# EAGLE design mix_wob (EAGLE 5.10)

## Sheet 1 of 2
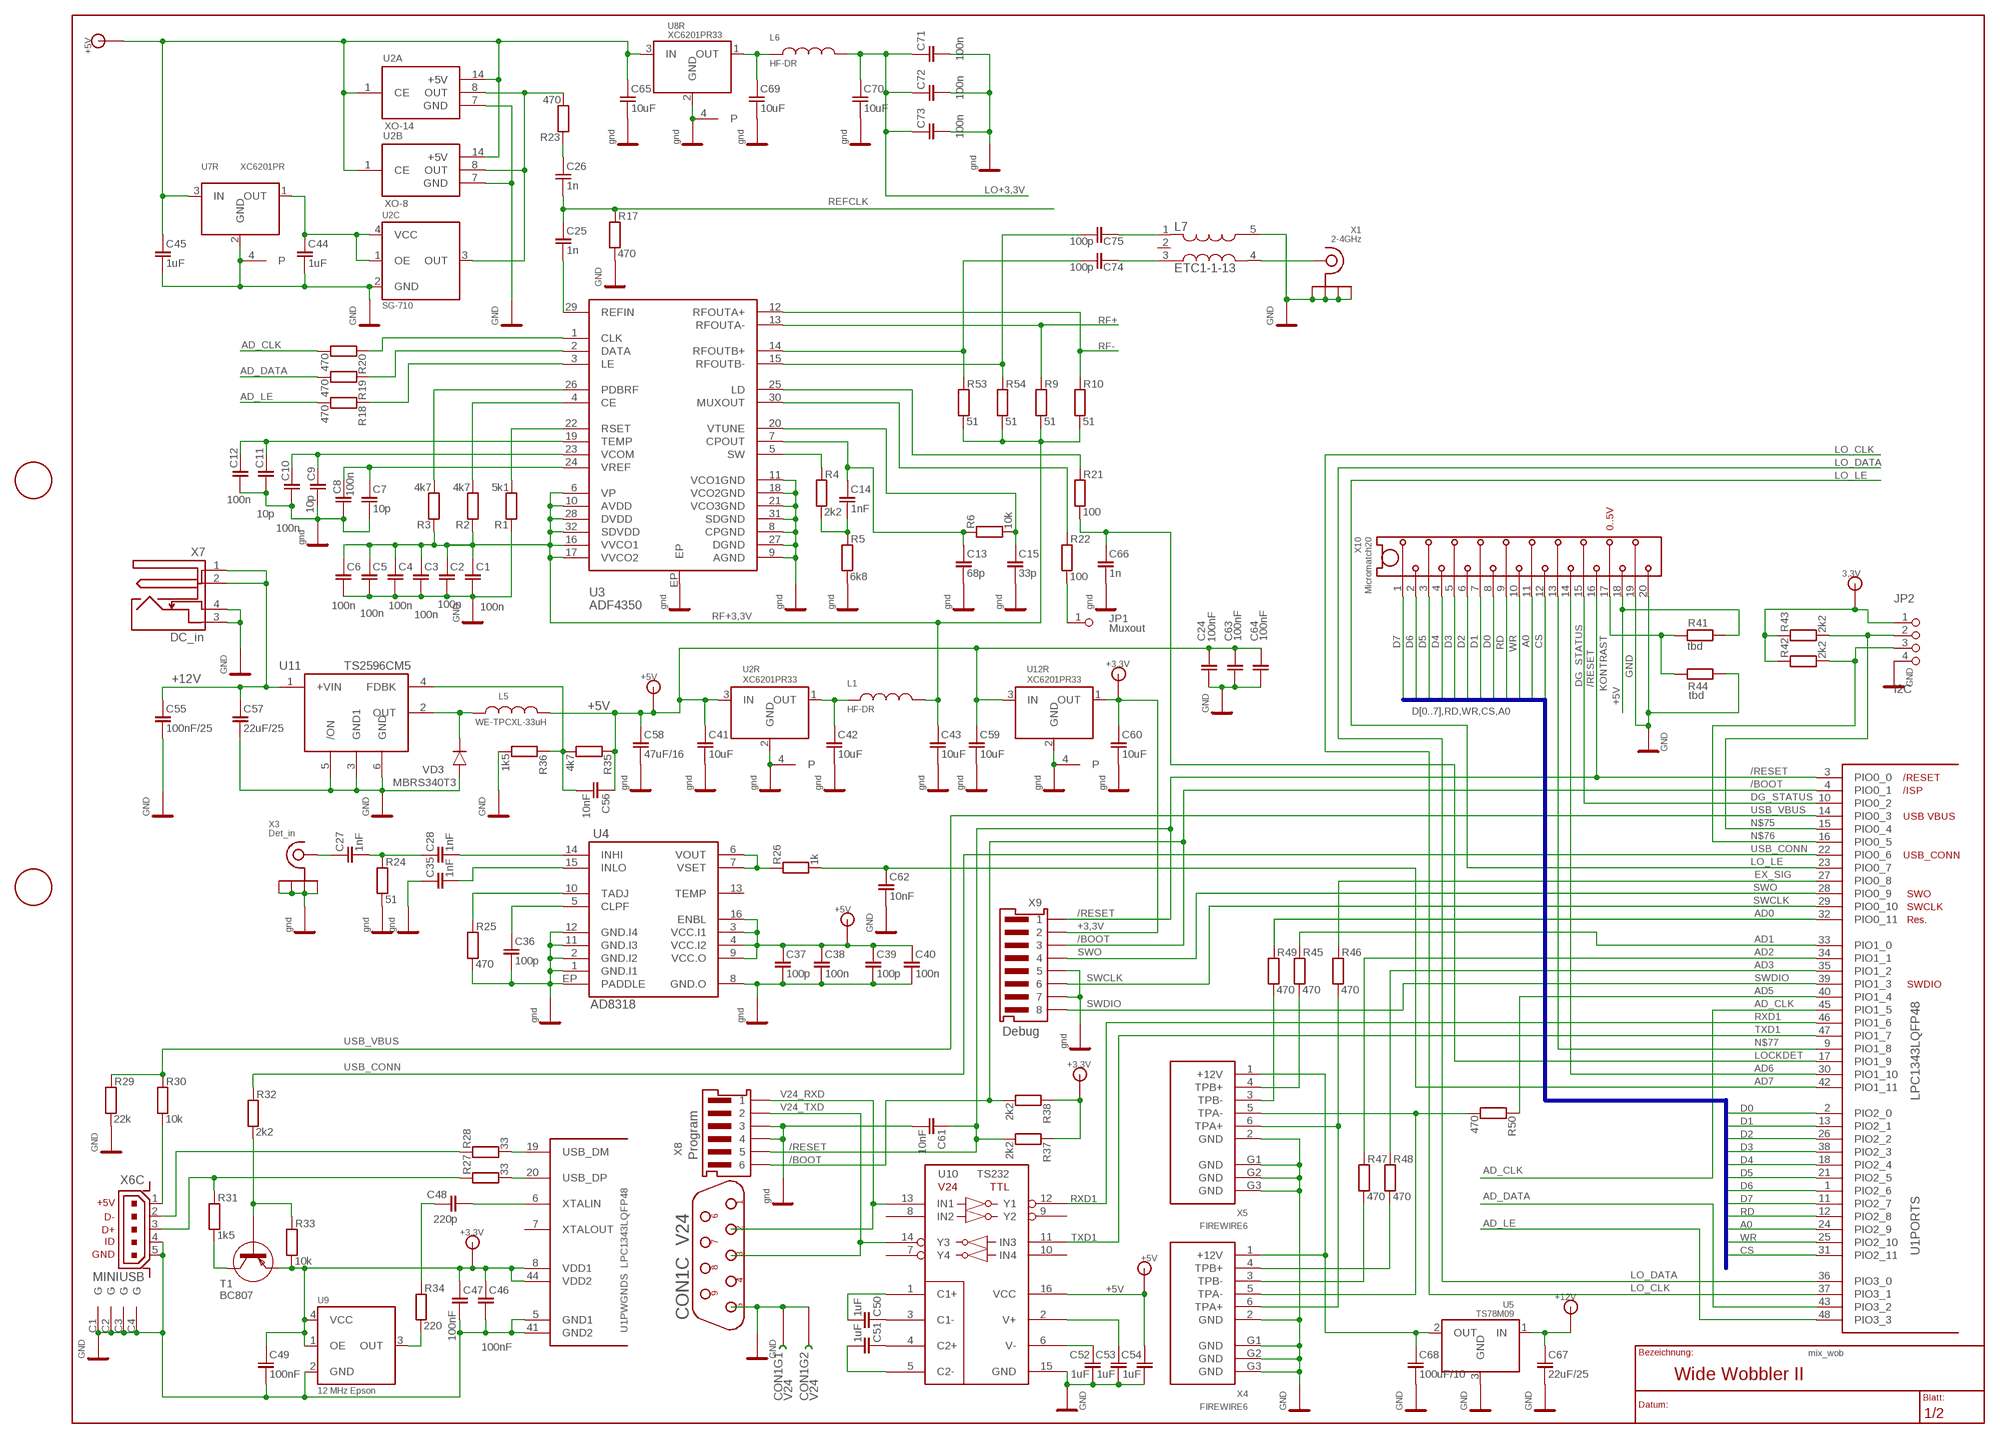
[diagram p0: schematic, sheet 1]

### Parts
C1  100n  SMD-0603  [SOT-0603]
C2  100n  SMD-0603  [SOT-0603]
C3  100n  SMD-0603  [SOT-0603]
C4  100n  SMD-0603  [SOT-0603]
C5  100n  SMD-0603  [SOT-0603]
C6  100n  SMD-0603  [SOT-0603]
C7  10p  SMD-0603  [SOT-0603]
C8  100n  SMD-0603  [SOT-0603]
C9  10p  SMD-0603  [SOT-0603]
C10  100n  SMD-0603  [SOT-0603]
C11  10p  SMD-0603  [SOT-0603]
C12  100n  SMD-0603  [SOT-0603]
C13  68p  SMD-0603  [SOT-0603]
C14  1nF  SMD-0603  [SOT-0603]
C15  33p  SMD-0603  [SOT-0603]
C24  100nF  SMD-0603  [SOT-0603]
C25  1n  SMD-0603  [SOT-0603]
C26  1n  SMD-0603  [SOT-0603]
C27  1nF  SMD-0603  [SOT-0603]
C28  1nF  SMD-0603  [SOT-0603]
C35  1nF  SMD-0603  [SOT-0603]
C36  100p  SMD-0603  [SOT-0603]
C37  100p  SMD-0603  [SOT-0603]
C38  100n  SMD-0603  [SOT-0603]
C39  100p  SMD-0603  [SOT-0603]
C40  100n  SMD-0603  [SOT-0603]
C41  10uF  SMD-0805  [SOT-0805]
C42  10uF  SMD-0805  [SOT-0805]
C43  10uF  SMD-0805  [SOT-0805]
C44  1uF  SMD-0805  [SOT-0805]
C45  1uF  SMD-0805  [SOT-0805]
C46  100nF  SMD-0603  [SOT-0603]
C47  100nF  SMD-0603  [SOT-0603]
C48  220p  SMD-0603  [SOT-0603]
C49  100nF  SMD-0603  [SOT-0603]
C50  1uF  SMD-0805  [SOT-0805]
C51  1uF  SMD-0805  [SOT-0805]
C52  1uF  SMD-0805  [SOT-0805]
C53  1uF  SMD-0805  [SOT-0805]
C54  1uF  SMD-0805  [SOT-0805]
C55  100nF/25  SMD-0805  [SOT-0805]
C56  10nF  SMD-0805  [SOT-0805]
C57  22uF/25  SMD-1210  [SOT-1210]
C58  47uF/16  SMD-1210  [SOT-1210]
C59  10uF  SMD-0805  [SOT-0805]
C60  10uF  SMD-0805  [SOT-0805]
C61  10nF  SMD-0603  [SOT-0603]
C62  10nF  SMD-0603  [SOT-0603]
C63  100nF  SMD-0603  [SOT-0603]
C64  100nF  SMD-0603  [SOT-0603]
C65  10uF  SMD-0805  [SOT-0805]
C66  1n  SMD-0603  [SOT-0603]
C67  22uF/25  SMD-1210  [SOT-1210]
C68  100uF/10  SMD-1210  [SOT-1210]
C69  10uF  SMD-0805  [SOT-0805]
C70  10uF  SMD-0805  [SOT-0805]
C71  100n  SMD-0603  [SOT-0603]
C72  100n  SMD-0603  [SOT-0603]
C73  100n  SMD-0603  [SOT-0603]
C74  100p  SMD-0603  [SOT-0603]
C75  100p  SMD-0603  [SOT-0603]
CON1  V24  DB9M/90  [DZ09M/90]
JP1  Muxout  PINHD-1X1  [1X01]
JP2  I2C  PINHD-1X4  [1X04]
L1  HF-DR  SMD-0805  [SMD-0805]
L5  WE-TPCXL-33uH  WE-TPCXL  [WE-TPCXL]
L6  HF-DR  SMD-0805  [SMD-0805]
L7  ETC1-1-13  [ETC1-1-13]
R1  5k1  SMD-0603  [SMD-0603]
R2  4k7  SMD-0603  [SMD-0603]
R3  4k7  SMD-0603  [SMD-0603]
R4  2k2  SMD-0603  [SMD-0603]
R5  6k8  SMD-0603  [SMD-0603]
R6  10k  SMD-0603  [SMD-0603]
R9  51  SMD-0603  [SMD-0603]
R10  51  SMD-0603  [SMD-0603]
R17  470  SMD-0603  [SMD-0603]
R18  470  SMD-0603  [SMD-0603]
R19  470  SMD-0603  [SMD-0603]
R20  470  SMD-0603  [SMD-0603]
R21  100  SMD-0603  [SMD-0603]
R22  100  SMD-0603  [SMD-0603]
R23  470  SMD-0603  [SMD-0603]
R24  51  SMD-0603  [SMD-0603]
R25  470  SMD-0603  [SMD-0603]
R26  1k  SMD-0603  [SMD-0603]
R27  33  SMD-0603  [SMD-0603]
R28  33  SMD-0603  [SMD-0603]
R29  22k  SMD-0603  [SMD-0603]
R30  10k  SMD-0603  [SMD-0603]
R31  1k5  SMD-0603  [SMD-0603]
R32  2k2  SMD-0603  [SMD-0603]
R33  10k  SMD-0603  [SMD-0603]
R34  220  SMD-0603  [SMD-0603]
R35  4k7  SMD-0805  [SMD-0805]
R36  1k5  SMD-0805  [SMD-0805]
R37  2k2  SMD-0603  [SMD-0603]
R38  2k2  SMD-0603  [SMD-0603]
R41  tbd  SMD-0603  [SMD-0603]
R42  2k2  SMD-0603  [SMD-0603]
R43  2k2  SMD-0603  [SMD-0603]
R44  tbd  SMD-0603  [SMD-0603]
R45  470  SMD-0603  [SMD-0603]
R46  470  SMD-0603  [SMD-0603]
R47  470  SMD-0603  [SMD-0603]
R48  470  SMD-0603  [SMD-0603]
R49  470  SMD-0603  [SMD-0603]
R50  470  SMD-0603  [SMD-0603]
R53  51  SMD-0603  [SMD-0603]
R54  51  SMD-0603  [SMD-0603]
T1  BC807  BC807-40  [SOT-23]
U1  LPC1343LQFP48  LPC13XXLQFP48  [LQFP48]
U2  XC6201PR33  XC6201-PR  [SOT89]
U2A  XO-14  QU-OSZ14  [OSC]
U2B  XO-8  QU-OSZ8  [OSC-KURZ]
U2C  SG-710  [SG710]
U3  ADF4350  ADF4350CP-32-2  [CP32-2]
U4  AD8318  [CP16-4]
U5  TS78M09  TS78MXX  [DPAK]
U7  XC6201PR  XC6201-PR  [SOT89]
U8  XC6201PR33  XC6201-PR  [SOT89]
U9  12 MHz Epson  SG-710  [SG710]
U10  TS232  MAX-232CWE  [SO-16W]
U11  TS2596CM5  [TO263-5L]
U12  XC6201PR33  XC6201-PR  [SOT89]
VD3  MBRS340T3  [SMC]
X1  2-4GHz  SMA-EDGE'KANTE'  [SMA-EDGE]
X3  Det_in  SMA-EDGE'KANTE'  [SMA-EDGE]
X4  FIREWIRE6  [IEEE1394-6V]
X5  FIREWIRE6  [IEEE1394-6V]
X6  MINIUSB  [UX60A-MB-5SY]
X7  DC_in  DC-10-XX  [DC-10-XX]
X8  Program  LUMBG6  [LUMBG6]
X9  Debug  LUMBG8  [LUMBG8]
X10  Micromatch20  MICMATCH20  [MIMA20]

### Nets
+3,3V: C46.2 C47.2 C49.2 C60.2 JP2.1 R33.1 R37.2 R38.2 R42.2 R43.2 T1.2(E) U1.8(PWGNDS:VDD1) U1.44(PWGNDS:VDD2) U9.1(OE) U9.4(VCC) U12.1(R:OUT) X9.2 ; supply symbol labelled 3,3V
+3,3V_XO: C44.2 U2C.1(OE) U2C.4(VCC) U7.1(R:OUT)
+5V: C24.2 C37.2 C38.2 C39.2 C40.2 C41.2 C45.2 C54.2 C56.2 C58.2 C59.2 C63.2 C64.2 C65.2 L5.2 R35.2 R41.2 U2.3(R:IN) U2A.1(CE) U2A.14(+5V) U2B.1(CE) U2B.14(+5V) U4.3(VCC.I1) U4.4(VCC.I2) U4.9(VCC.O) U4.16(ENBL) U7.3(R:IN) U8.3(R:IN) U10.16(VCC) U12.3(R:IN) X10.18
+9VOLT: C68.2 U5.2(OUT) X4.1(+12V) X5.1(+12V)
+12V: C55.2 C57.2 C67.2 U5.1(IN) U11.1(+VIN) X7.1 X7.2
/BOOT: R38.1 U1.4(PORTS:PIO0_1) X8.6 X9.3
/RESET: C61.2 R37.1 U1.3(PORTS:PIO0_0) X8.5 X9.1 X10.16
A0: U1.24(PORTS:PIO2_9) X10.11
AD0: R49.2 U1.32(PORTS:PIO0_11)
AD1: R45.2 U1.33(PORTS:PIO1_0)
AD2: R47.2 U1.34(PORTS:PIO1_1)
AD3: R48.2 U1.35(PORTS:PIO1_2)
AD5: R50.2 U1.40(PORTS:PIO1_4)
AD6: U1.30(PORTS:PIO1_10) X10.14
AD7: C62.2 R26.1 U1.42(PORTS:PIO1_11)
AD_CLK: R20.1 U1.45(PORTS:PIO1_5)
AD_DATA: R19.1 U1.43(PORTS:PIO3_2)
AD_LE: R18.1 U1.48(PORTS:PIO3_3)
CS: U1.31(PORTS:PIO2_11) X10.12
D0: U1.2(PORTS:PIO2_0) X10.8
D1: U1.13(PORTS:PIO2_1) X10.7
D2: U1.26(PORTS:PIO2_2) X10.6
D3: U1.38(PORTS:PIO2_3) X10.5
D4: U1.18(PORTS:PIO2_4) X10.4
D5: U1.21(PORTS:PIO2_5) X10.3
D6: U1.1(PORTS:PIO2_6) X10.2
D7: U1.11(PORTS:PIO2_7) X10.1
DG_STATUS: U1.10(PORTS:PIO0_2) X10.15
EX_SIG: R46.2 U1.27(PORTS:PIO0_8)
F_REF: C26.2 R23.2
GND: C1.1 C2.1 C3.1 C4.1 C5.1 C6.1 C7.1 C8.1 C9.1 C10.1 C11.1 C12.1 C13.1 C15.1 C24.1 C35.2 C36.1 C37.1 C38.1 C39.1 C40.1 C41.1 C42.1 C43.1 C44.1 C45.1 C46.1 C47.1 C49.1 C52.1 C53.1 C54.1 C55.1 C57.1 C58.1 C59.1 C60.1 C61.1 C62.1 C63.1 C64.1 C65.1 C66.1 C67.1 C68.1 C69.1 C70.1 C71.1 C72.1 C73.1 CON1.5 CON1.G1 CON1.G2 JP2.4 L7.5 R1.2 R5.1 R17.1 R24.1 R25.1 R29.1 R36.1 R44.1 U1.5(PWGNDS:GND1) U1.41(PWGNDS:GND2) U2.2(R:GND) U2.4(P) U2A.7(GND) U2B.7(GND) U2C.2(GND) U3.8(CPGND) U3.9(AGND) U3.11(VCO1GND) U3.18(VCO2GND) U3.21(VCO3GND) U3.27(DGND) U3.31(SDGND) U3.EP U4.1(GND.I1) U4.2(GND.I2) U4.8(GND.O) U4.11(GND.I3) U4.12(GND.I4) U4.EP(PADDLE) U5.3(GND) U7.2(R:GND) U7.4(P) U8.2(R:GND) U8.4(P) U9.2(GND) U10.15(GND) U11.3(GND1) U11.5(/ON) U11.6(GND) U12.2(R:GND) U12.4(P) VD3.A X1.GND@1(GND) X1.GND@2(GND) X1.GND@3(GND) X1.GND@4(GND) X3.GND@1(GND) X3.GND@2(GND) X3.GND@3(GND) X3.GND@4(GND) X4.2(GND) X4.G1(GND) X4.G2(GND) X4.G3(GND) X5.2(GND) X5.G1(GND) X5.G2(GND) X5.G3(GND) X6.4 X6.5 X6.C1(G) X6.C2(G) X6.C3(G) X6.C4(G) X7.3 X7.4 X8.3 X8.4 X9.5 X9.7 X10.19 X10.20 ; supply symbol labelled gnd ; also sheet 2
KONTRAST: R41.1 R44.2 X10.17
LO+3,3V: C70.2 C71.2 C72.2 C73.2 L6.2 ; also sheet 2
LO_CLK: U1.37(PORTS:PIO3_1) ; also sheet 2
LO_DATA: U1.36(PORTS:PIO3_0) ; also sheet 2
LO_LE: U1.23(PORTS:PIO0_7) ; also sheet 2
LOCKDET: C66.2 R21.1 U1.17(PORTS:PIO1_9)
N$1: R18.2 U3.3(LE)
N$2: C7.2 C8.2 U3.24(VREF)
N$3: C9.2 C10.2 U3.23(VCOM)
N$4: C11.2 C12.2 U3.19(TEMP)
N$5: R1.1 U3.22(RSET)
N$7: R2.1 U3.4(CE)
N$8: R3.1 U3.26(PDBRF)
N$9: C15.2 R6.1 U3.20(VTUNE)
N$10: C14.1 R4.1 R5.2
N$11: R4.2 U3.5(SW)
N$12: C13.2 C14.2 R6.2 U3.7(CPOUT)
N$14: R19.2 U3.2(DATA)
N$15: R20.2 U3.1(CLK)
N$36: C69.2 L6.1 U8.1(R:OUT)
N$37: C75.2 L7.1
N$38: L7.4 X1.A
N$39: C74.2 L7.3
N$40: C25.1 U3.29(REFIN)
N$42: R21.2 U3.25(LD)
N$43: R22.2 U3.30(MUXOUT)
N$44: R23.1 U2A.8(OUT) U2B.8(OUT) U2C.3(OUT)
N$45: C27.2 X3.A
N$46: C27.1 C28.2 R24.2
N$47: C28.1 U4.14(INHI)
N$48: C35.1 U4.15(INLO)
N$49: C36.2 U4.5(CLPF)
N$50: R25.2 U4.10(TADJ)
N$51: R26.2 U4.6(VOUT) U4.7(VSET)
N$52: C42.2 L1.1 U2.1(R:OUT)
N$53: R27.2 R31.2 X6.3
N$54: R28.2 X6.2
N$55: R30.1 X6.1
N$56: R28.1 U1.19(PWGNDS:USB_DM)
N$57: R27.1 U1.20(PWGNDS:USB_DP)
N$58: R31.1 T1.3(C)
N$59: R32.1 R33.2 T1.1(B)
N$60: C48.1 U1.6(PWGNDS:XTALIN)
N$61: C48.2 R34.2
N$62: R34.1 U9.3(OUT)
N$63: C50.1 U10.1(C1+)
N$64: C50.2 U10.3(C1-)
N$65: C51.2 U10.4(C2+)
N$66: C51.1 U10.5(C2-)
N$67: C52.2 U10.6(V-)
N$68: C53.2 U10.2(V+)
N$70: JP1.1 R22.1
N$71: C75.1 R54.2 U3.15(RFOUTB-)
N$72: C74.1 R53.2 U3.14(RFOUTB+)
N$73: L5.1 U11.2(OUT) VD3.K
N$74: C56.1 R35.1 R36.2 U11.4(FDBK)
N$75: JP2.2 R43.1 U1.15(PORTS:PIO0_4)
N$76: JP2.3 R42.1 U1.16(PORTS:PIO0_5)
N$77: U1.9(PORTS:PIO1_8) X10.13
N$78: R48.1 X4.4(TPB+)
N$79: R47.1 X4.3(TPB-)
N$80: R45.1 X5.4(TPB+)
N$81: R49.1 X5.3(TPB-)
N$82: R46.1 X4.6(TPA+) X5.6(TPA+)
N$83: R50.1 X4.5(TPA-) X5.5(TPA-)
RD: U1.12(PORTS:PIO2_8) X10.9
REFCLK: C25.2 C26.1 R17.2 ; also sheet 2
RF+: R9.2 U3.13(RFOUTA-) ; also sheet 2
RF+3,3V: C1.2 C2.2 C3.2 C4.2 C5.2 C6.2 C43.2 L1.2 R2.2 R3.2 R9.1 R10.1 R53.1 R54.1 U3.6(VP) U3.10(AVDD) U3.16(VVCO1) U3.17(VVCO2) U3.28(DVDD) U3.32(SDVDD)
RF-: R10.2 U3.12(RFOUTA+) ; also sheet 2
RXD1: U1.46(PORTS:PIO1_6) U10.12(Y1)
SWCLK: U1.29(PORTS:PIO0_10) X9.6
SWDIO: U1.39(PORTS:PIO1_3) X9.8
SWO: U1.28(PORTS:PIO0_9) X9.4
TXD1: U1.47(PORTS:PIO1_7) U10.11(IN3)
USB_CONN: R32.2 U1.22(PORTS:PIO0_6)
USB_VBUS: R29.2 R30.2 U1.14(PORTS:PIO0_3)
V24_RXD: CON1.2 U10.13(IN1) X8.1
V24_TXD: CON1.3 U10.14(Y3) X8.2
WR: U1.25(PORTS:PIO2_10) X10.10
Unconnected: CON1.1 CON1.4 CON1.6 CON1.7 CON1.8 CON1.9 L7.2 U1.7(PWGNDS:XTALOUT) U4.13(TEMP) U10.7(Y4) U10.8(IN2) U10.9(Y2) U10.10(IN4)

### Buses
D[0..7],RD,WR,CS,A0

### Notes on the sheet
- 0..5V
- Wide Wobbler II

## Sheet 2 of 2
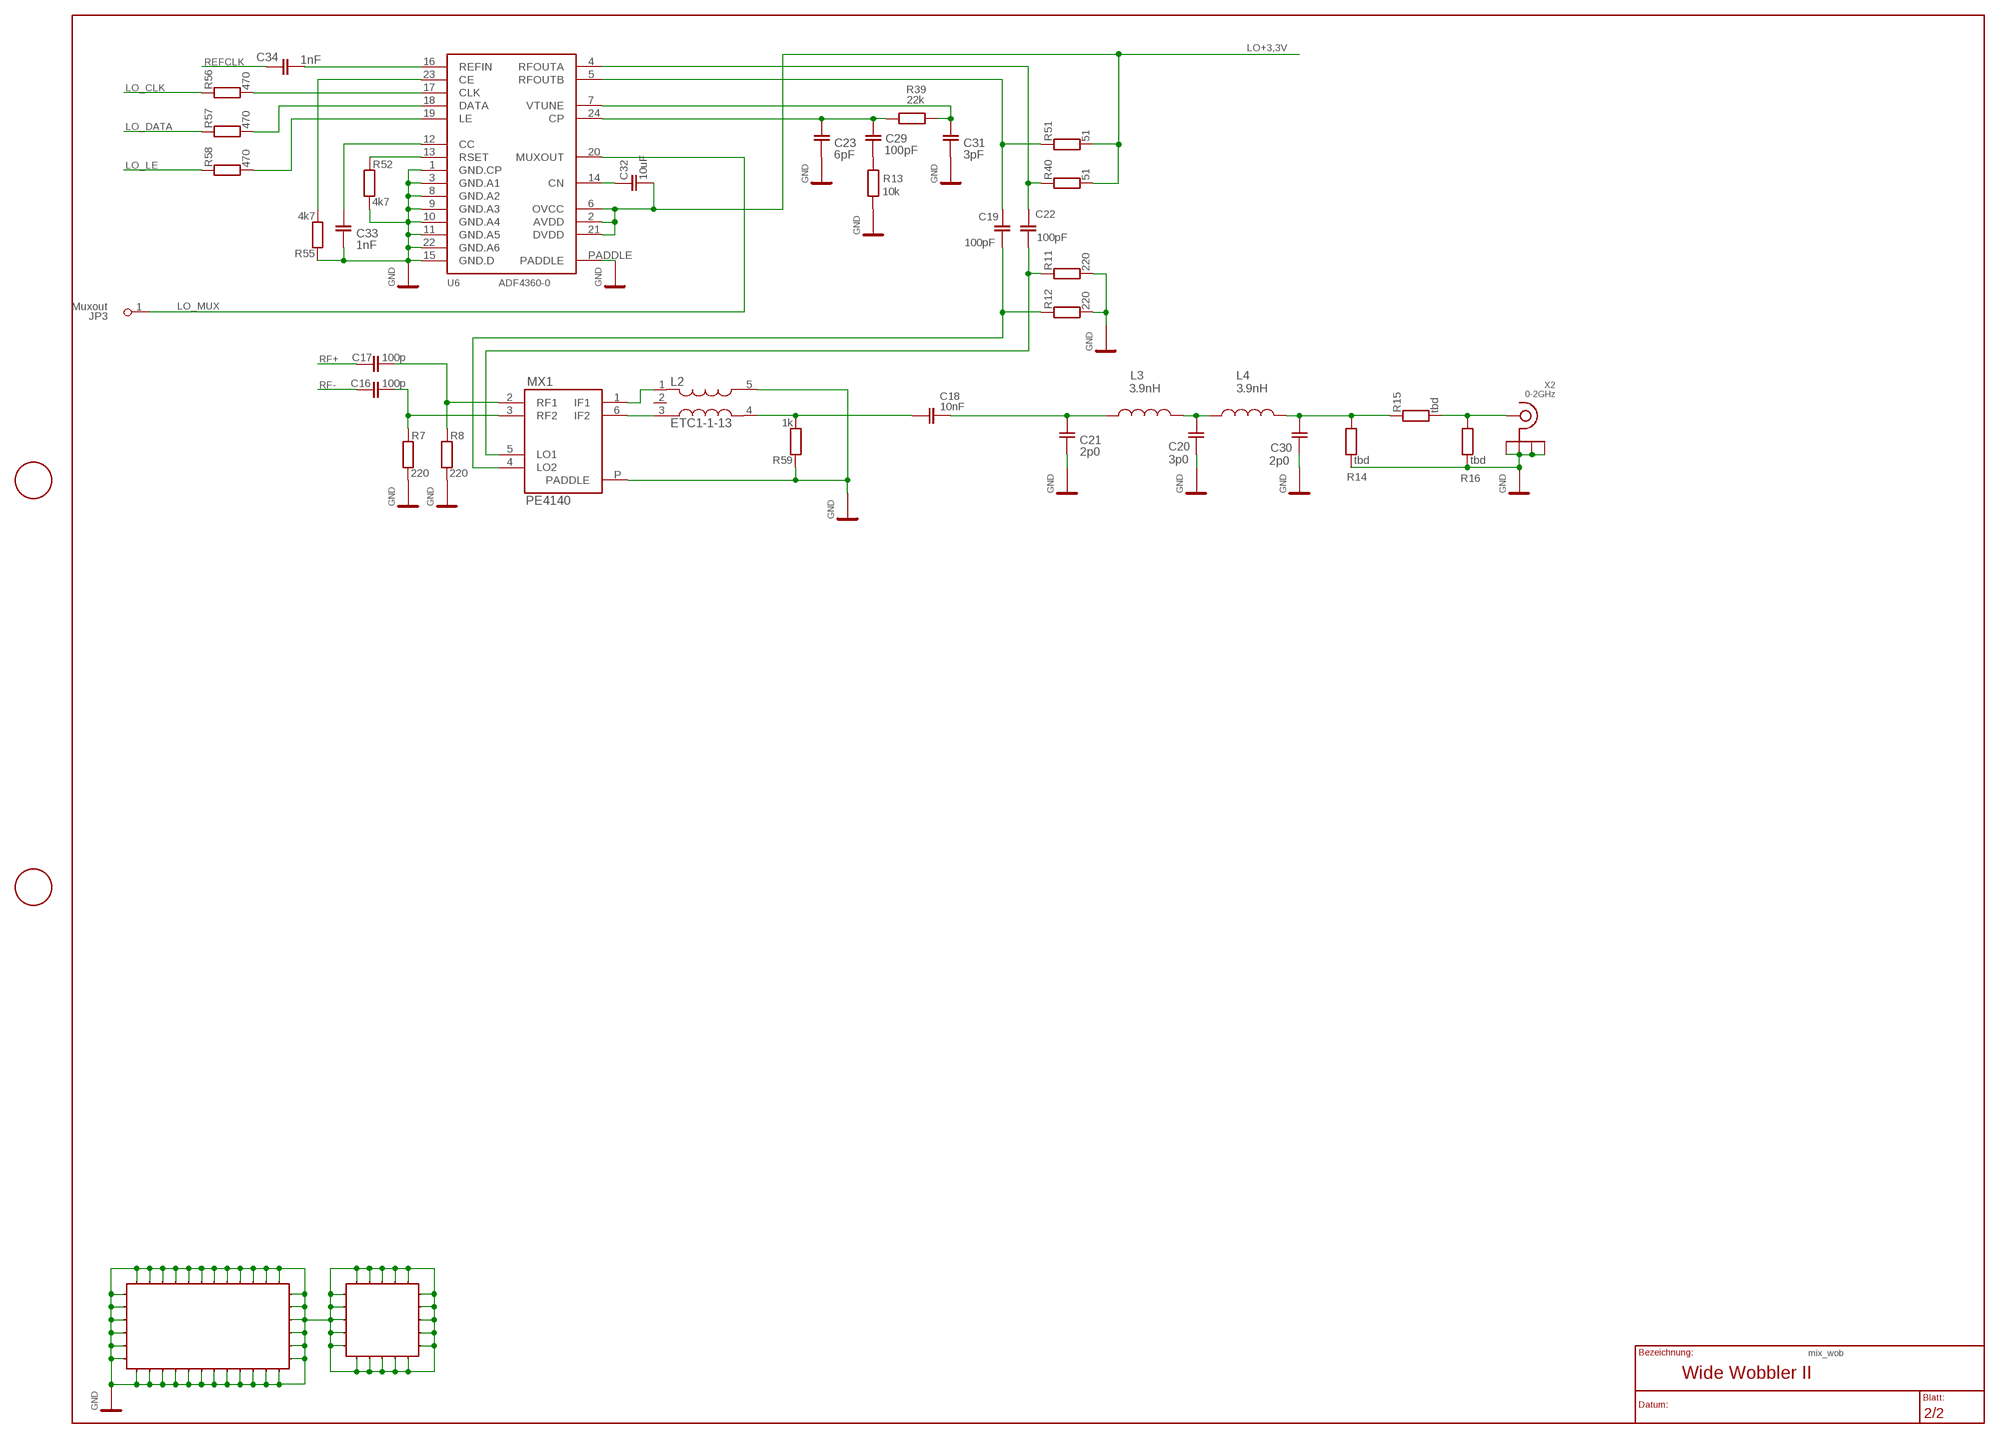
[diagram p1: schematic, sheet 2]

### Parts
C16  100p  SMD-0603  [SOT-0603]
C17  100p  SMD-0603  [SOT-0603]
C18  10nF  SMD-0603  [SOT-0603]
C19  100pF  SMD-0603  [SOT-0603]
C20  3p0  SMD-0603  [SOT-0603]
C21  2p0  SMD-0603  [SOT-0603]
C22  100pF  SMD-0603  [SOT-0603]
C23  6pF  SMD-0603  [SOT-0603]
C29  100pF  SMD-0603  [SOT-0603]
C30  2p0  SMD-0603  [SOT-0603]
C31  3pF  SMD-0603  [SOT-0603]
C32  10uF  SMD-0805  [SOT-0805]
C33  1nF  SMD-0603  [SOT-0603]
C34  1nF  SMD-0603  [SOT-0603]
JP3  Muxout  PINHD-1X1  [1X01]
L2  ETC1-1-13  [ETC1-1-13]
L3  3.9nH  SMD-0603  [SMD-0603]
L4  3.9nH  SMD-0603  [SMD-0603]
MX1  PE4140  [PE4140]
R7  220  SMD-0603  [SMD-0603]
R8  220  SMD-0603  [SMD-0603]
R11  220  SMD-0603  [SMD-0603]
R12  220  SMD-0603  [SMD-0603]
R13  10k  SMD-0603  [SMD-0603]
R14  tbd  SMD-0603  [SMD-0603]
R15  tbd  SMD-0603  [SMD-0603]
R16  tbd  SMD-0603  [SMD-0603]
R39  22k  SMD-0603  [SMD-0603]
R40  51  SMD-0603  [SMD-0603]
R51  51  SMD-0603  [SMD-0603]
R52  4k7  SMD-0603  [SMD-0603]
R55  4k7  SMD-0603  [SMD-0603]
R56  470  SMD-0603  [SMD-0603]
R57  470  SMD-0603  [SMD-0603]
R58  470  SMD-0603  [SMD-0603]
R59  1k  SMD-0603  [SMD-0603]
S1  Shield-Gen  S31-62  [AK31X62]
S2  Shield-Det  S25-25  [AK25X25]
U6  ADF4360-0  ADF4360-X  [CP-24-3]
X2  0-2GHz  SMA-EDGE'KANTE'  [SMA-EDGE]

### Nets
GND: C20.1 C21.1 C23.1 C30.2 C31.1 C33.1 L2.5 MX1.P(PADDLE) R7.1 R8.1 R11.1 R12.1 R13.1 R14.1 R16.1 R52.1 R55.2 R59.2 S1.1 S1.2 S1.3 S1.4 S1.5 S1.6 S1.7 S1.8 S1.9 S1.10 S1.11 S1.12 S1.13 S1.14 S1.15 S1.16 S1.17 S1.18 S1.19 S1.20 S1.21 S1.22 S1.23 S1.24 S1.25 S1.26 S1.27 S1.28 S1.29 S1.30 S1.31 S1.32 S1.33 S1.34 S1.35 S1.36 S2.1 S2.2 S2.3 S2.4 S2.5 S2.6 S2.7 S2.8 S2.9 S2.10 S2.11 S2.12 S2.13 S2.14 S2.15 S2.16 S2.17 S2.18 S2.19 S2.20 U6.1(GND.CP) U6.3(GND.A1) U6.8(GND.A2) U6.9(GND.A3) U6.10(GND.A4) U6.11(GND.A5) U6.15(GND.D) U6.22(GND.A6) U6.PADDLE X2.GND@1(GND) X2.GND@2(GND) X2.GND@3(GND) X2.GND@4(GND) ; also sheet 1
LO+3,3V: C32.1 R40.1 R51.1 U6.2(AVDD) U6.6(OVCC) U6.21(DVDD) ; also sheet 1
LO_CLK: R56.2 ; also sheet 1
LO_DATA: R57.2 ; also sheet 1
LO_LE: R58.2 ; also sheet 1
LO_MUX: JP3.1 U6.20(MUXOUT)
N$6: R55.1 U6.23(CE)
N$13: L2.3 MX1.6(IF2)
N$16: R56.1 U6.17(CLK)
N$17: R57.1 U6.18(DATA)
N$18: L2.1 MX1.1(IF1)
N$19: C22.2 R40.2 U6.4(RFOUTA)
N$20: C16.1 MX1.3(RF2) R7.2
N$21: C17.1 MX1.2(RF1) R8.2
N$22: C30.1 L4.2 R14.2 R15.2
N$23: C19.2 R51.2 U6.5(RFOUTB)
N$24: C18.1 C21.2 L3.1
N$25: C20.2 L3.2 L4.1
N$26: C22.1 MX1.5(LO1) R11.2
N$27: R15.1 R16.2 X2.A
N$28: C19.1 MX1.4(LO2) R12.2
N$29: C29.1 R13.2
N$30: C23.2 C29.2 R39.2 U6.24(CP)
N$31: C31.2 R39.1 U6.7(VTUNE)
N$32: C32.2 U6.14(CN)
N$33: R52.2 U6.13(RSET)
N$34: C33.2 U6.12(CC)
N$35: C34.1 U6.16(REFIN)
N$41: R58.1 U6.19(LE)
N$69: C18.2 L2.4 R59.1
REFCLK: C34.2 ; also sheet 1
RF+: C17.2 ; also sheet 1
RF-: C16.2 ; also sheet 1
Unconnected: L2.2

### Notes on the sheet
- Wide Wobbler II

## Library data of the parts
C1-C31 C33-C40 C46-C49 C61-C64 C66 C71-C75 = C_KERAM:SMD-0603
C32 C41-C45 C50-C56 C59 C60 C65 C69 C70 = C_KERAM:SMD-0805
C57 C58 C67 C68 = C_KERAM:SMD-1210
CON1 = Z_CONNEC:DB9M/90
JP1 JP3 = PINHD-Q:PINHD-1X1
JP2 = PINHD-Q:PINHD-1X4
L1 L6 = L:SMD-0805
L2 L7 = HAMRAD:ETC1-1-13: MACOM Transmission-Line Balun 4.5 - 3000 MHz
L3 L4 = L:SMD-0603
L5 = L:WE-TPCXL
MX1 = HAMRAD:PE4140: MOSFET-Array
R1-R34 R37-R59 = R:SMD-0603
R35 R36 = R:SMD-0805
S1 = SHIELDS:S31-62
S2 = SHIELDS:S25-25
T1 = TR_PNP:BC807-40
U1 = philips:LPC13XX
U2 U7 U8 U12 = TOREX:XC6201-PR
U2A = Z_SPECIA:QU-OSZ14
U2B = Z_SPECIA:QU-OSZ8
U2C U9 = SEIK_EPS:SG-710
U3 = ANALOG_D:ADF4350: 4.4 GHz Synthesizer mit integriertem VCO
U4 = ANALOG_D:AD8318
U5 = TSC:TS78MXX
U6 = HAMRAD:ADF4360-X
U10 = MAXIM:MAX-232CWE
U11 = TSC:TS2596CM5
VD3 = DIODEN:MBRS340T3
X1-X3 = HAMRAD:SMA-EDGE
X4 X5 = Z_CONNEC:FIREWIRE6
X6 = mini-usb:MINIUSB
X7 = Z_CONNEC:DC-10-XX
X8 = Z_CONNEC:LUMBG6
X9 = Z_CONNEC:LUMBG8
X10 = TYCO:MICMATCH20

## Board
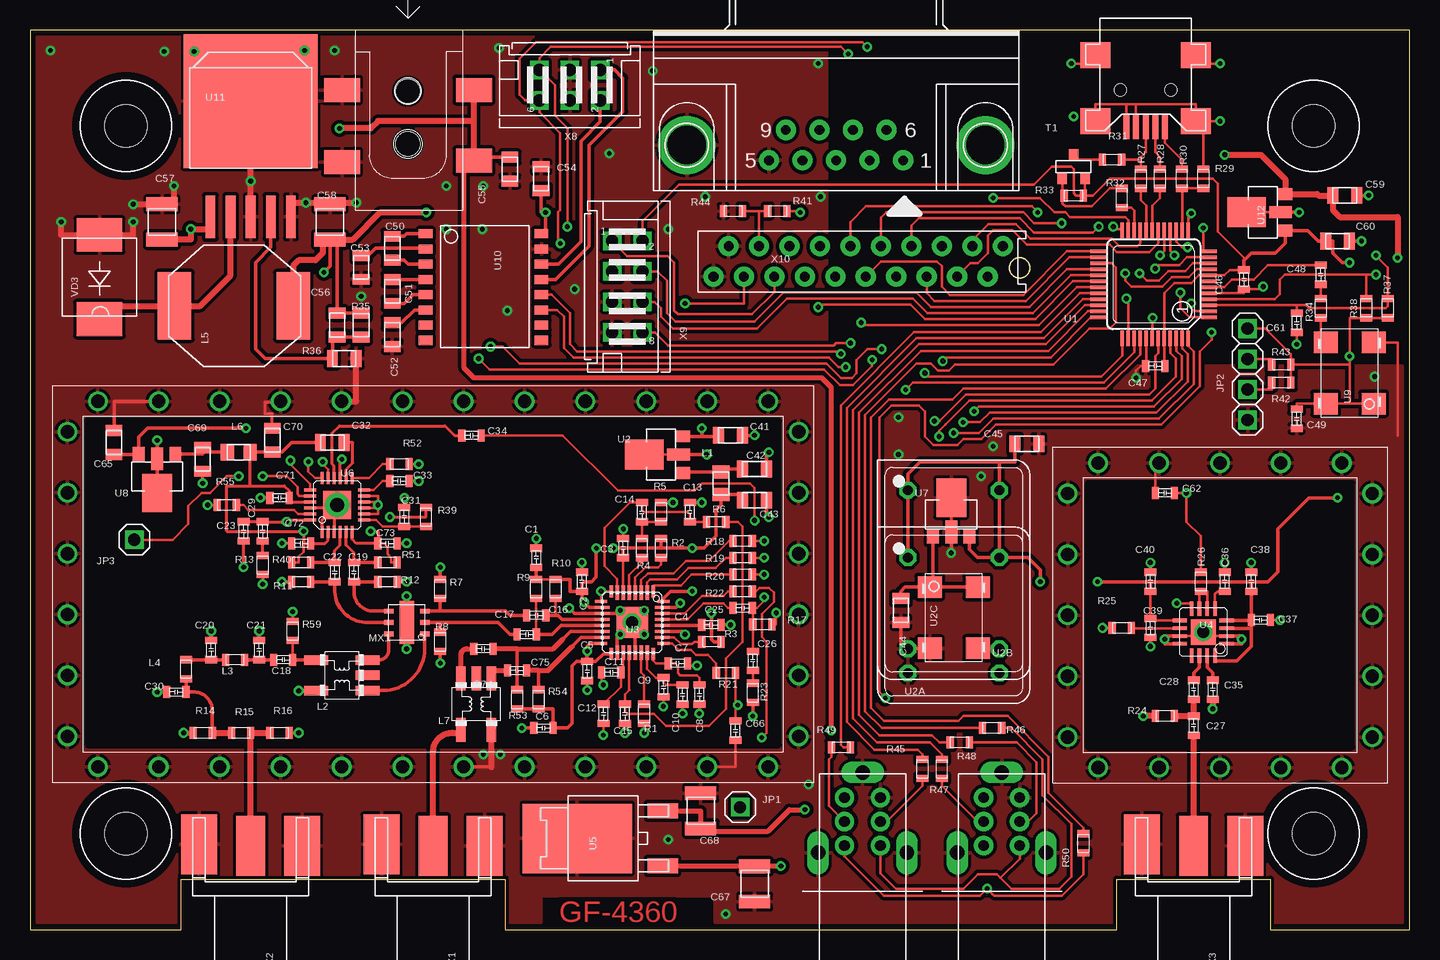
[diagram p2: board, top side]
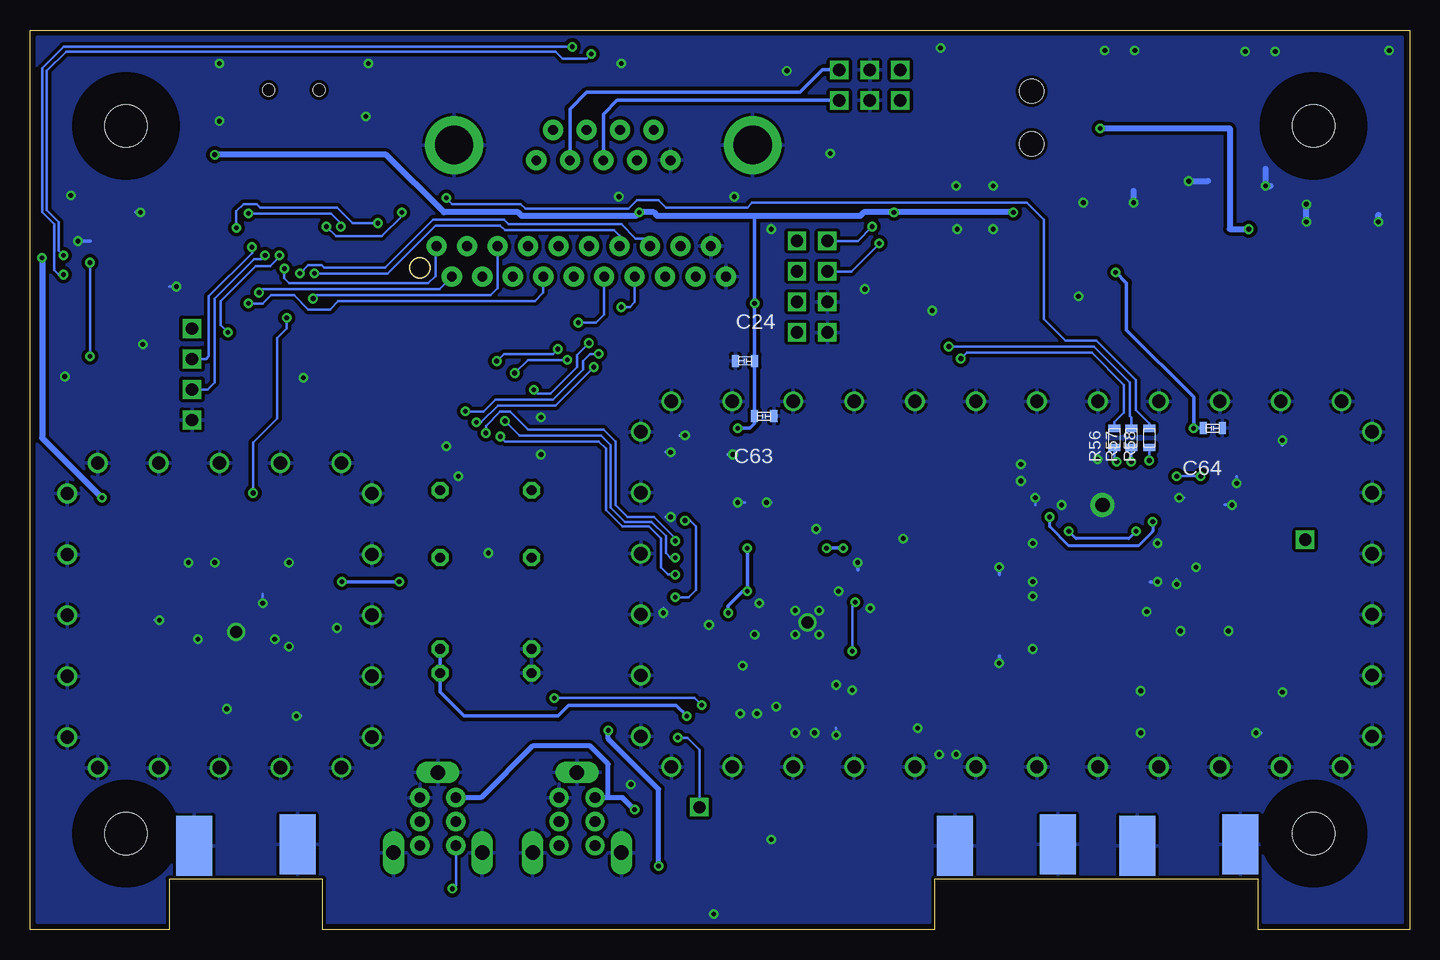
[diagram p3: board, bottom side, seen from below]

Size 115 x 75 mm. Coordinates in mm from the lower left corner, seen from the top.
Outline: 0,0 12.6,0 12.6,4.2 39.6,4.2 39.6,0 90.6,0 90.6,4.2 103.4,4.2 103.4,0 115,0 115,75 0,75 0,0
Copper layers (1*16): Top 0.035mm / dielectric 1.5mm / Bottom 0.035mm
Design rules "alles02": minimum track width 0.2mm, minimum drill 0.4mm, track to track 0.2mm, track to pad 0.2mm, pad to pad 0.2mm, via to via 0.2mm, smd to smd 0mil, copper to edge 0.15mm, drill to drill 0.15mm, minimum pad ring 0.15mm, minimum via ring 0.15mm, stop-mask expansion 4mil, vias tented up to drill 0mil, thermal gap 10mil
tRestrict: area 4.8,15.4 to 62.4,42.4; area 88.2,15.2 to 110.2,37.2

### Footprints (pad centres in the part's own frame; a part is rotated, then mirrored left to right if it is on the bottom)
SOT-0603 = smd 0.6 x 1: 1 -0.8,0; 2 0.8,0
SOT-0805 = smd 0.914 x 1.397: 1 -0.991,0; 2 0.991,0
SOT-1210 = smd 1.143 x 2.591: 1 -1.473,0; 2 1.473,0
DZ09M/90 = drill 0.813 pad 1.676 round: 1 5.588,-1.27; 2 2.794,-1.27; 3 0,-1.27; 4 -2.794,-1.27; 5 -5.588,-1.27; 6 4.191,1.27; 7 1.397,1.27; 8 -1.397,1.27; 9 -4.191,1.27 | drill 3.2 pad 4.064 round: G1 12.446,0; G2 -12.446,0
1X01 = drill 1.016 pad 1.524 square: 1 0,0
1X04 = drill 1.016 pad 1.575 square: 1 -3.81,0; 2 -1.27,0; 3 1.27,0; 4 3.81,0
SMD-0805 = smd 1.092 x 1.397: 1 -0.94,0; 2 0.94,0
ETC1-1-13 = smd 0.8 x 2: 1 1.27,2.14; 2 0,2.14; 3 -1.27,2.14; 4 -1.27,-2.14; 5 1.27,-2.14
SMD-0603 = smd 0.6 x 1: 1 -0.8,0; 2 0.8,0
WE-TPCXL = smd 5.588 x 2.794: 1 0,4.953; 2 0,-4.953
PE4140 = smd 0.4 x 0.8: 1 -0.95,-1.5; 2 0,-1.5; 3 0.95,-1.5; 4 0.95,1.5; 5 0,1.5; 6 -0.95,1.5 | smd 3.6 x 1.2: P 0,0
SMD-0805' = smd 0.914 x 1.397: 1 -0.991,0; 2 0.991,0
AK31X62 = drill 1.1 pad 1.6 round: 1 -15.24,-27.94; 2 -15.24,-2.54; 3 -15.24,2.54; 4 -15.24,7.62; 5 -15.24,27.94; 6 -12.7,30.48; 7 -2.54,30.48; 8 2.54,30.48; 9 -15.24,22.86; 10 12.7,30.48; 11 15.24,27.94; 12 15.24,7.62; 13 15.24,2.54; 14 15.24,-2.54; 15 15.24,-27.94; 16 12.7,-30.48; 17 -15.24,17.78; 18 2.54,-30.48; 19 -2.54,-30.48; 20 -12.7,-30.48; 21 15.24,12.7; 22 -15.24,12.7; 23 -15.24,-7.62; 24 15.24,-7.62; 25 15.24,22.86; 26 15.24,17.78; 27 -15.24,-12.7; 28 -15.24,-17.78; 29 15.24,-12.7; 30 15.24,-17.78; 31 15.24,-22.86; 32 -15.24,-22.86; 33 -7.62,30.48; 34 7.62,30.48; 35 -7.62,-30.48; 36 7.62,-30.48
AK25X25 = drill 1.1 pad 1.6 round: 1 -12.7,-10.16; 2 -12.7,-5.08; 3 -12.7,0; 4 -12.7,5.08; 5 -12.7,10.16; 6 -10.16,12.7; 7 -5.08,12.7; 8 0,12.7; 9 5.08,12.7; 10 10.16,12.7; 11 12.7,10.16; 12 12.7,5.08; 13 12.7,0; 14 12.7,-5.08; 15 12.7,-10.16; 16 10.16,-12.7; 17 5.08,-12.7; 18 0,-12.7; 19 -5.08,-12.7; 20 -10.16,-12.7
SOT-23 = smd 0.787 x 0.889: 1 0.94,1.016; 2 -0.94,1.016; 3 0,-1.016
LQFP48 = smd 0.279 x 1.27: 1 -2.75,-4.5; 2 -2.25,-4.5; 3 -1.75,-4.5; 4 -1.25,-4.5; 5 -0.75,-4.5; 6 -0.25,-4.5; 7 0.25,-4.5; 8 0.75,-4.5; 9 1.25,-4.5; 10 1.75,-4.5; 11 2.25,-4.5; 12 2.75,-4.5; 25 2.75,4.75; 26 2.25,4.75; 27 1.75,4.75; 28 1.25,4.75; 29 0.75,4.75; 30 0.25,4.75; 31 -0.25,4.75; 32 -0.75,4.75; 33 -1.25,4.75; 34 -1.75,4.75; 35 -2.25,4.75; 36 -2.75,4.75 | smd 1.27 x 0.279: 13 4.5,-2.75; 14 4.5,-2.25; 15 4.5,-1.75; 16 4.5,-1.25; 17 4.5,-0.75; 18 4.5,-0.25; 19 4.5,0.25; 20 4.5,0.75; 21 4.5,1.25; 22 4.5,1.75; 23 4.5,2.25; 24 4.5,2.75; 37 -4.5,2.75; 38 -4.5,2.25; 39 -4.5,1.75; 40 -4.5,1.25; 41 -4.5,0.75; 42 -4.5,0.25; 43 -4.5,-0.25; 44 -4.5,-0.75; 45 -4.5,-1.25; 46 -4.5,-1.75; 47 -4.5,-2.25; 48 -4.5,-2.75
SOT89 = smd 0.991 x 1.194: 1 -1.524,-1.829; 3 1.524,-1.829 | smd 0.991 x 1.905: 2 0,-1.448 | smd 2.5 x 3.2: 4 0,1.4
OSC = drill 0.813 pad 1.397 octagon: 1 -7.62,-3.81; 7 7.62,-3.81; 8 7.62,3.81; 14 -7.62,3.81
OSC-KURZ = drill 0.813 pad 1.397 octagon: 1 -3.81,-3.81; 7 3.81,-3.81; 8 3.81,3.81; 14 -3.81,3.81
SG710 = smd 1.8 x 2: 1 -2.55,-2; 2 2.55,-2; 3 2.55,2; 4 -2.55,2
CP32-2 = smd 1 x 0.28: 1 -2.6,1.75; 8 -2.6,-1.75; 17 2.6,-1.75; 24 2.6,1.75 | smd 1.2 x 0.28: 2 -2.5,1.25; 3 -2.5,0.75; 4 -2.5,0.25; 5 -2.5,-0.25; 6 -2.5,-0.75; 7 -2.5,-1.25; 18 2.5,-1.25; 19 2.5,-0.75; 20 2.5,-0.25; 21 2.5,0.25; 22 2.5,0.75; 23 2.5,1.25 | smd 0.28 x 1: 9 -1.75,-2.6; 16 1.75,-2.6; 25 1.75,2.6; 32 -1.75,2.6 | smd 0.28 x 1.2: 10 -1.25,-2.5; 11 -0.75,-2.5; 12 -0.25,-2.5; 13 0.25,-2.5; 14 0.75,-2.5; 15 1.25,-2.5; 26 1.25,2.5; 27 0.75,2.5; 28 0.25,2.5; 29 -0.25,2.5; 30 -0.75,2.5; 31 -1.25,2.5 | smd 2.6 x 2.6: EP 0,0
CP16-4 = smd 1.2 x 0.3: 1 -1.95,0.975; 2 -1.95,0.325; 3 -1.95,-0.325; 4 -1.95,-0.975; 9 1.95,-0.975; 10 1.95,-0.325; 11 1.95,0.325; 12 1.95,0.975 | smd 0.3 x 1.2: 5 -0.975,-1.95; 6 -0.325,-1.95; 7 0.325,-1.95; 8 0.975,-1.95; 13 0.975,1.95; 14 0.325,1.95; 15 -0.325,1.95; 16 -0.975,1.95 | smd 2.1 x 2.1: EP 0,0
DPAK = smd 1.27 x 2.54: 1 -2.286,-2.032; 2 2.286,-2.032 | smd 5.8 x 9.1: 3 0,5.08
CP-24-3 = smd 1 x 0.28: 1 -2.25,1.25; 2 -2.25,0.75; 3 -2.25,0.25; 4 -2.25,-0.25; 5 -2.25,-0.75; 6 -2.25,-1.25; 13 2.25,-1.25; 14 2.25,-0.75; 15 2.25,-0.25; 16 2.25,0.25; 17 2.25,0.75; 18 2.25,1.25 | smd 0.28 x 1: 7 -1.25,-2.25; 8 -0.75,-2.25; 9 -0.25,-2.25; 10 0.25,-2.25; 11 0.75,-2.25; 12 1.25,-2.25; 19 1.25,2.25; 20 0.75,2.25; 21 0.25,2.25; 22 -0.25,2.25; 23 -0.75,2.25; 24 -1.25,2.25 | smd 2.3 x 2.3: PADDLE 0,0
SO-16W = smd 0.762 x 1.143: 1 -3.81,-4.826; 2 -2.54,-4.826; 3 -1.27,-4.826; 4 0,-4.826; 5 1.27,-4.826; 6 2.54,-4.826; 7 3.81,-4.826; 8 5.08,-4.826; 9 5.08,4.826; 10 3.81,4.826; 11 2.54,4.826; 12 1.27,4.826; 13 0,4.826; 14 -1.27,4.826; 15 -2.54,4.826; 16 -3.81,4.826
TO263-5L = smd 0.813 x 3.556: 1 -3.353,-8.382; 2 -1.676,-8.382; 3 0,-8.382; 4 1.676,-8.382; 5 3.353,-8.382 | smd 11.176 x 11.176: 6 0,1.27
DRIL-3,5 = hole 3.556: 0,0
SMC = smd 2.794 x 3.81: A 3.505,0; K -3.505,0
SMA-EDGE = smd 5 x 2.4: A 0,0 | smd 5 x 3: GND@1 0,4.3; GND@2 -0.1,-4.3 | smd 5 x 3 bottom: GND@3 0,4.3; GND@4 -0.1,-4.3
IEEE1394-6V = drill 0.9 pad 1.6 round: 1 4,1.5; 2 4,-1.5; 3 2,1.5; 4 2,-1.5; 5 0,1.5; 6 0,-1.5 | drill 1.2 long: G1 6.1,0; G2 -0.6,3.7; G3 -0.6,-3.7
UX60A-MB-5SY = smd 0.5 x 2: 1 -1.6,3.1; 2 -0.8,3.1; 3 0,3.1; 4 0.8,3.1; 5 1.6,3.1 | smd 2.5 x 2.2: C1 -4.2,2.6; C2 -4.2,-2.9; C3 4.2,-2.9; C4 4.2,2.6 | hole 1.016: -2.1,0; 2.1,0
DC-10-XX = smd 3 x 2: 1 5.5,-5.9; 2 5.5,0; 3 -5.5,0; 4 -5.5,-6 | hole 2: 0,-0.1; 0,-4.5
LUMBG6 = drill 1.016 pad 1.422 square: 1 -1.27,2.54; 2 1.27,2.54; 3 -1.27,0; 4 1.27,0; 5 -1.27,-2.54; 6 1.27,-2.54
LUMBG8 = drill 1.016 pad 1.422 square: 1 -1.27,3.81; 2 1.27,3.81; 3 -1.27,1.27; 4 1.27,1.27; 5 -1.27,-1.27; 6 1.27,-1.27; 7 -1.27,-3.81; 8 1.27,-3.81
MIMA20 = drill 0.813 pad 1.676 round: 1 0,1.27; 2 -1.27,-1.27; 3 -2.54,1.27; 4 -3.81,-1.27; 5 -5.08,1.27; 6 -6.35,-1.27; 7 -7.62,1.27; 8 -8.89,-1.27; 9 -10.16,1.27; 10 -11.43,-1.27; 11 -12.7,1.27; 12 -13.97,-1.27; 13 -15.24,1.27; 14 -16.51,-1.27; 15 -17.78,1.27; 16 -19.05,-1.27; 17 -20.32,1.27; 18 -21.59,-1.27; 19 -22.86,1.27; 20 -24.13,-1.27 | hole 1.676: 1.4,-0.53

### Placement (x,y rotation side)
C1  42.2,31 270 top
C2  46,29 270 top
C3  49.45,31.8 270 top
C4  56.8,25.4 180 top
C5  46.45,21.55 90 top
C6  42.8,16.8 0 top
C7  54,22.2 180 top
C8  55.8,19.6 90 top
C9  52.8,20.2 90 top
C10  54.4,19.6 90 top
C11  48.45,21.45 0 top
C12  47.8,18 90 top
C13  55,34.8 270 top
C14  51,34.8 90 top
C15  49.6,18 90 top
C16  42.2,26.2 0 top
C17  41.4,24.6 0 top
C18  21.1,22.5 0 top
C19  27,29.8 90 top
C20  15.1,23.3 270 top
C21  19.1,23.3 270 top
C22  25.4,29.8 90 top
C23  17.8,33.2 90 top
C24  55.4,47.4 0 bottom
C25  59.4,26.8 0 top
C26  60.25,22.4 270 top
C27  97,17 270 top
C28  97,20 270 top
C29  19.4,33.2 90 top
C30  12.2,19.8 180 top
C31  31.2,34.4 270 top
C32  25.2,40.6 0 top
C33  30.8,37.4 180 top
C34  36.8,41.2 0 top
C35  98.6,20 270 top
C36  99.6,29 270 top
C37  102.6,25.8 180 top
C38  101.8,29 270 top
C39  93.4,25.15 90 top
C40  93.4,29 270 top
C41  58.4,41.2 180 top
C42  60.4,38.4 180 top
C43  60.4,35.8 180 top
C44  72.6,26.6 90 top
C45  83.1,40.5 180 top
C46  101.2,54.2 90 top
C47  93.8,47 0 top
C48  107.6,54.6 270 top
C49  105.6,42.6 90 top
C50  30.2,56.8 270 top
C51  30.2,53.2 90 top
C52  30.2,49.6 90 top
C53  27.6,55.2 90 top
C54  42.6,62.6 270 top
C55  40,63.4 90 top
C56  25.6,50.4 90 top
C57  11,59 270 top
C58  25,59 270 top
C59  109.6,61.2 180 top
C60  109,57.4 180 top
C61  105.6,50.6 90 top
C62  94.6,36.4 0 top
C63  53.8,42.8 180 bottom
C64  16.4,41.8 180 bottom
C65  7,40.6 270 top
C66  58.8,16.6 90 top
C67  60.4,3.8 90 top
C68  55.9,9.9 270 top
C69  14.4,39.2 90 top
C70  20.2,40.8 270 top
C71  20.8,36 0 top
C72  22.6,32.2 0 top
C73  29.8,32.2 180 top
C74  37.8,23.4 180 top
C75  40.6,21.6 180 top
CON1  67.2,65.4 0 top
JP1  59.2,10.2 0 top
JP2  101.5,46.3 270 top
JP3  8.7,32.5 0 top
L1  57.6,37.2 270 top
L2  26,21.2 270 top
L3  17.1,22.5 180 top
L4  13,21.7 270 top
L5  17,52 90 top
L6  17.4,39.8 0 top
L7  37.2,18.8 0 top
MX1  31.4,25.6 90 top
R1  51.2,18 270 top
R2  52.6,31.8 90 top
R3  56.8,24 0 top
R4  51,31.8 270 top
R5  52.6,34.8 270 top
R6  57.2,34 180 top
R7  34.2,28.4 270 top
R8  34.2,24 90 top
R9  42.2,28.4 270 top
R10  43.8,28.4 270 top
R11  22.6,29 0 top
R12  29.8,29 180 top
R13  19.4,30.4 90 top
R14  14.4,16.4 0 top
R15  17.6,16.4 180 top
R16  20.8,16.4 180 top
R17  61.05,25.45 180 top
R18  59.4,32.4 180 top
R19  59.4,31 180 top
R20  59.4,29.6 180 top
R21  58,21.4 180 top
R22  59.4,28.2 180 top
R23  60.25,19.75 90 top
R24  94.6,17.8 0 top
R25  91,25.15 0 top
R26  97.6,29 270 top
R27  92.6,62.6 90 top
R28  94.2,62.6 90 top
R29  97.8,62.6 270 top
R30  96,62.6 270 top
R31  90.2,64.2 0 top
R32  91,61 270 top
R33  87,61.2 180 top
R34  107.6,51.8 90 top
R35  4k7  [SMD-0805']  27.6,50.4 90 top
R36  1k5  [SMD-0805']  26.2,47.6 180 top
R37  113.2,51.8 270 top
R38  111.4,51.8 270 top
R39  33,34.4 90 top
R40  22.6,30.6 0 top
R41  62.3,59.9 0 top
R42  104.3,45.6 0 top
R43  104.3,47.1 0 top
R44  58.6,59.9 0 top
R45  74.4,13.4 90 top
R46  80.2,16.8 180 top
R47  76,13.4 90 top
R48  77.5,15.6 180 top
R49  67.6,15.2 0 top
R50  87.8,7.2 90 top
R51  29.8,30.6 180 top
R52  30.8,38.8 180 top
R53  40.6,19.2 90 top
R54  42.4,19.2 90 top
R55  16.4,35.4 180 top
R56  24.6,41 90 bottom
R57  23.2,41 90 bottom
R58  21.7,41 90 bottom
R59  21.9,24.9 90 top
S1  33.6,28.8 270 top
S2  99.2,26.2 0 top
T1  87,63.6 180 top
U1  93.8,53.8 90 top
U2  52.6,39.6 90 top
U2A  77,29 270 top
U2B  77,27.2 270 top
U2C  77,26 270 top
U3  50.2,25.6 270 top
U4  97.8,24.8 180 top
U5  50.7,7.6 90 top
U6  25.6,35.4 90 top
U7  76.8,34.6 0 top
U8  10.6,37.8 180 top
U9  110,46.4 90 top
U10  37.8,54.2 270 top
U11  18.4,67.8 0 top
U12  102.8,59.8 90 top
U$51  [DRIL-3,5]  107,8 0 top
U$52  [DRIL-3,5]  8,8 0 top
U$53  [DRIL-3,5]  107,67 0 top
U$54  [DRIL-3,5]  8,67 0 top
VD3  5.8,54.4 90 top
X1  33.6,7 270 top
X2  18.4,7 270 top
X3  97,7 270 top
X4  81,7 90 top
X5  69.4,7 90 top
X6  93,70 180 top
X7  31.5,70 0 top
X8  45,70.4 270 top
X9  49.8,53.6 0 top
X10  81.1,55.7 0 top

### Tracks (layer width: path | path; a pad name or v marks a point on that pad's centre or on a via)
+3,3V  (via drill 0.4 pad 0.8)
  Top 0.2: C49.2 105.6,43.85 U9.4 U9.1 110,43.85 110,47.1 | 110,47.1 v110,47.8 110,51 R38.2 R37.2 | C47.2 94.55,47.05 U1.44 94.55,53.05 95.4,53.9 96.8,53.9 97.45,54.55 U1.8 99.55,54.55 100,55 C46.2 | T1.2 87.94,61.2 R33.1 | R33.1 88.6,61.2 90,62.6 98.6,62.6 99,62.2 99,58.2 101.3,55.9 | R33.1 87.2,61.2 87,61.4 87,63.4 86.8,63.6 85.2,63.6 83.7,62.1 54.1,62.1 51.07,59.07 X9.2 | JP2.1 102.99,50.11 105.1,48 R43.2 | 110,47.1 R43.2 | R43.2 R42.2
  Top 0.3: C46.2 101.2,55.8 101.3,55.9 101.8,56.4 103.8,56.4 104.63,57.23 U12.1 106.52,58.28 107.4,57.4 C60.2 108.6,57.4 108.6,56.4 109.4,55.6 v110,55.6
  Bottom 0.2: v110,55.6 v110,47.8
+3,3V_XO
  Top 0.3: U7.1 75.28,28.55 U2C.1 | U2C.1 U2C.4 | U2C.1 72.95,28.55 72.6,28.2 C44.2
+5V  (via drill 0.4 pad 0.8)
  Top 0.2: 98.78,22.4 U4.16 | C37.2 101.8,25.77 | U4.9 93.4,25.77 C39.2 C40.2 | X10.18 59.51,52.2 v54.6,52.2 | R41.2 64.1,59.9 v64.2,59.8
  Top 0.3: 98.78,22.4 100.6,22.4 101.8,23.6 101.8,25.12 | 101.8,25.77 U4.4 | 101.8,25.12 U4.3 | 101.8,25.12 C37.2 C38.2 101.8,29 | 93.4,29 C40.2 | 101.8,29 93.4,29 | 93.4,29 v89,29 | U2B.1 U2A.1 73.19,37.99 74.2,39 80.81,39 | U2B.14 U2A.14 80.81,39 | v84.22,29 84.22,29.98 83.19,31.01 U2B.14 | U2B.14 78.99,31.01 78.32,31.68 U7.3 | C45.2 82.11,39 80.81,39 | 25.6,57.53 C56.2 R35.2 | C41.2 57.41,41.12 U2.3 56,41.12 v56,41.8 | v24.5,54.8 25,55.3 C58.2 | 101.8,29 103.2,29 104,29.8 104,33.4 106.6,36 v109,36 | v18,41.8 9.8,41.8 9.08,41.08 U8.3 9.08,39.61 C65.2 | U10.16 42.98,58.01 v42.98,59.8 42.6,59.8 C54.2
  Top 0.5: L5.2 21.95,55.35 22.4,55.8 23.8,55.8 24.4,56.4 24.4,57.53 C58.2 25.6,57.53 26.93,57.53 29.2,59.8 v33.03,59.8 | v99.6,64.6 102.6,64.6 104.63,62.57 U12.3 107.28,61.32 107.4,61.2 C59.2 108.61,59.99 109.2,59.4 114,59.4 v114,56
  Bottom 0.3: v89,29 v84.22,29 | v24.5,54.8 23.6,53.9 23.6,50 18,44.4 v18,41.8 C64.2 | v56,41.8 55,41.8 54.6,42.2 C63.2 C24.2 v54.6,52.2 54.6,59.5
  Bottom 0.5: v33.03,59.8 v42.98,59.8 45.5,59.8 45.8,59.5 54.6,59.5 62.7,59.5 63,59.8 v64.2,59.8 64.5,59.5 74,59.5 74.3,59.8 80.5,59.8 85.3,64.6 v99.6,64.6 | v114,56 114,41 v109,36
+9VOLT  (via drill 0.4 pad 0.8)
  Top 0.4: U5.2 55.9,9.89 C68.2 56.13,8.2 61.5,8.2 63.3,10 v64.6,10
  Bottom 0.4: 66.8,11 65.6,11 v64.6,10 | X4.1 77.4,11 73.1,15.3 68.3,15.3 66.8,13.8 66.8,11 | 66.8,11 X5.1
+12V  (via drill 0.4 pad 0.8)
  Top 0.2: C67.2 60.43,5.3
  Top 0.3: 37.1,64.39 C55.2
  Top 0.4: v66.8,16.6 66.8,45.2 66,46 37,46 36.2,46.8 36.2,64.39 | 60.43,5.3 v62.6,5.3 | U5.1 60.36,5.31 C67.2
  Top 0.5: C57.2 13.4,57.53 v13.4,58.4 15.05,58.4 U11.1 | v25.8,66.8 28.4,66.8 29,67.4 37,67.4 | 36.2,64.39 37.1,64.39 37.1,64.1 X7.1 37,67.4 | 37,67.4 X7.2
  Bottom 0.4: v66.8,16.6 66.8,15.9 62.6,11.7 v62.6,5.3
  Bottom 0.5: v13.4,58.4 15,58.4 15,66.8 v25.8,66.8
/BOOT  (via drill 0.4 pad 0.8)
  Top 0.2: v69.8,73.6 69.4,74 42.2,74 40.8,72.6 40.8,69.6 41.27,69.13 X8.6 42.46,68.14 44.2,66.4 44.2,60 44,59.8 44,57.4 v44.2,57.2 | U1.4 103.75,52.55 104.2,53 104.2,54.2 104.6,54.6 111.4,54.6 | v112.2,54.6 111.4,54.6 | 111.4,54.6 R38.1
  Bottom 0.2: v69.8,73.6 112.2,73.6 114,71.8 114,59.8 113,58.8 113,55 112.6,54.6 v112.2,54.6 | X9.3 46.53,54.87 v44.2,57.2
/RESET  (via drill 0.4 pad 0.8)
  Top 0.2: v68.2,73 67.6,73.6 43.4,73.6 42.46,72.66 X8.5 43.75,70.38 43.75,67.85 44.8,66.8 v44.8,58.6 | 105.6,52.05 106.35,52.05 106.6,51.8 113,51.8 113.2,52 R37.1 113.2,55.2 v112.2,56.2 | 105.6,52.05 U1.3 | 105.6,52.05 C61.2 | X10.16 62.05,53.15 60.2,51.3 54,51.3 53.7,51.6 53.7,55.6 53.15,56.15 49.79,56.15 X9.1
  Bottom 0.2: v68.2,73 68.6,72.6 70.6,72.6 71.2,73.2 112,73.2 113.6,71.6 113.6,60 112.6,59 112.6,56.6 v112.2,56.2 | X9.1 45.99,57.41 v44.8,58.6
A0  (via drill 0.4 pad 0.8)
  Top 0.2: X10.11 68.4,59 69.7,60.3 70.1,60.3 70.3,60.3 83.5,60.3 v84,59.8 | U1.24 91.05,58.4 90.5,58.4 v90.3,58.6
  Bottom 0.2: v84,59.8 84,59.7 84,59.5 85.7,57.8 89.5,57.8 v90.3,58.6
AD0
  Top 0.2: U1.32 87.5,53.05 84.25,49.8 73.7,49.8 67.6,43.7 67.6,15.4 67.8,15.2 R49.2
AD1
  Top 0.2: R45.2 74.4,14.6 74,15 70.4,15 68.1,17.3 68.1,43.5 73.9,49.3 84.5,49.3 87.75,52.55 U1.33
AD2
  Top 0.2: U1.34 87.95,52.05 84.7,48.8 74.1,48.8 68.6,43.3 68.6,17.6 70.6,15.6 75,15.6 76,14.6 R47.2
AD3
  Top 0.2: U1.35 88.2,51.55 84.9,48.25 74.25,48.25 69.1,43.1 69.1,17.9 70.8,16.2 75.2,16.2 75.8,15.6 R48.2
AD5
  Top 0.2: U1.40 92.55,47.95 89.7,45.1 77.8,45.1 76.9,44.2 71.6,44.2 70.1,42.7 70.1,18.5 71.2,17.4 77.4,17.4 77.8,17.8 81.5,17.8 84.9,14.4 84.9,11.4 87.8,8.5 R50.2
AD6  (via drill 0.4 pad 0.8)
  Top 0.2: U1.30 86.95,54.05 83.8,50.9 74.6,50.9 73.4,52.1 65.9,52.1 v65.7,51.9
  Bottom 0.2: 65.4,51.9 v65.7,51.9 65,51.9 64.59,52.31 X10.14
AD7  (via drill 0.4 pad 0.8)
  Top 0.2: R26.1 97.6,32.8 96.4,34 v96.4,36.4 C62.2 | U1.42 93.55,50.95 v93.6,51
  Bottom 0.2: v93.6,51 93.6,50.1 94.4,49.3 94.4,42.6 96.4,40.6 v96.4,36.4
AD_CLK  (via drill 0.4 pad 0.8)
  Top 0.2: R20.1 v61.2,29.6 | U1.45 95.05,48.05 95.5,47.6 95.5,46.1 93.5,44.1 78.3,44.1 76.3,42.1 75.8,41.6 v75.8,41.1
  Bottom 0.2: v61.2,29.6 61.8,29.6 62.4,30.2 62.4,32.6 63.4,33.6 65.6,33.6 67,35 67,40.1 67.6,40.7 74.9,40.7 75.2,40.7 75.4,40.7 v75.8,41.1
AD_DATA  (via drill 0.4 pad 0.8)
  Top 0.2: R19.1 v61.2,31 | v75.4,42.4 75.8,42.4 78,44.6 93.3,44.6 93.8,45.1 93.8,47.8 94.05,48.05 U1.43
  Bottom 0.2: v61.2,31 61.6,31 62,31.4 62,32.8 63.2,34 65.4,34 66.6,35.2 66.6,40.4 67.4,41.2 73.7,41.2 74,41.2 74.2,41.2 v75.4,42.4
AD_LE  (via drill 0.4 pad 0.8)
  Top 0.2: R18.1 v61.2,32.4 | v77,41.4 79.1,41.4 80.3,42.6 94.1,42.6 97,45.5 97,48.2 96.55,48.65 U1.48
  Bottom 0.2: v61.2,32.4 61.2,32.6 63,34.4 65.2,34.4 66.2,35.4 66.2,40.7 67.2,41.7 73.5,41.7 75,43.2 75.8,43.2 77,42 v77,41.4
CS  (via drill 0.4 pad 0.8)
  Top 0.2: U1.31 87.25,53.55 84.1,50.4 69.5,50.4 v69.3,50.6
  Bottom 0.2: X10.12 67.13,51.27 67.8,50.6 v69.3,50.6
D0  (via drill 0.4 pad 0.8)
  Top 0.2: v96.8,52.2 96.8,51.8 97.05,51.55 U1.2
  Bottom 0.2: v96.8,52.2 95.6,52.2 94.9,52.9 93,52.9 91.8,51.7 90,51.7 89.3,52.4 72.9,52.4 72.21,53.09 X10.8
D1  (via drill 0.4 pad 0.8)
  Top 0.2: X10.7 73.48,58.68 74.1,59.3 74.2,59.3 74.3,59.3 82.5,59.3 83.7,58.1 88.6,58.1 v89.1,58.6 | U1.13 96.55,59.45 v96.8,59.7
  Bottom 0.2: v89.1,58.6 89.1,58.9 89.9,59.7 v96.8,59.7
D2
  Top 0.2: U1.26 86.65,56.05 83,52.4 81.55,52.4 76.05,52.4 75.4,52.4 74.75,53.05 X10.6
D3  (via drill 0.4 pad 0.8)
  Top 0.2: U1.38 91.55,52.45 v91.4,52.6
  Bottom 0.2: v91.4,52.6 91.1,52.9 76.6,52.9 76.02,53.48 X10.5
D4
  Top 0.2: U1.18 94.05,57.25 93.3,56.5 90.6,56.5 90,57.1 83.1,57.1 81.9,58.3 80.3,58.3 79.85,57.85 79.85,56.4 79,55.55 78.41,55.55 X10.4
D5
  Top 0.2: X10.3 78.56,57.46 79.9,58.8 82.2,58.8 83.4,57.6 90.2,57.6 90.8,57 92.3,57 92.55,57.25 U1.21
D6  (via drill 0.4 pad 0.8)
  Top 0.2: U1.1 96.65,51.05 95.9,51.8 v95.9,53.1
  Bottom 0.2: X10.2 80.86,53.4 95.6,53.4 v95.9,53.1
D7  (via drill 0.4 pad 0.8)
  Top 0.2: v93.8,55.1 94.1,55.4 95.3,55.4 95.8,55.4 96.45,56.05 U1.11
  Bottom 0.2: v93.8,55.1 93.8,54.3 93.4,53.9 81.8,53.9 81.2,54.5 81.2,56.87 X10.1
DG_STATUS  (via drill 0.4 pad 0.8)
  Top 0.2: U1.10 96.95,55.55 96.3,54.9 94.9,54.9 94.1,54.1 93.1,54.1 v92.5,54.7
  Bottom 0.2: X10.15 63.32,57.62 64.52,57.62 65.7,58.8 75.1,58.8 75.5,59.2 81.4,59.2 85.4,55.2 90.5,55.2 90.7,55.4 91.8,55.4 v92.5,54.7
EX_SIG
  Top 0.2: U1.27 90.15,55.55 90.5,55.2 90.5,50.6 90,50.1 88.3,50.1 85.3,47.1 77.1,47.1 76.6,46.6 75.7,46.6 75.1,47.2 73.9,47.2 69.6,42.9 69.6,18.2 71,16.8 R46.2
F_REF
  Top 0.2: R23.2 C26.2
GND  (via drill 0.4 pad 0.8, 1 pad 0.8, 1.2 pad 2)
  Top 0.2: 50.66,24.6 v51.2,24.6 | v54.2,27.2 53.87,26.87 | v46.45,19.95 C5.1 | C11.1 47.65,20.55 v47.8,20.4 | C12.1 v47.8,16.2 | C15.1 v49.6,16.4 | C10.1 v54.4,18 | C8.1 v55.8,18 | R1.2 v51.2,16.4 | C7.1 54.8,22 v55.6,22 | R17.1 62.2,25.45 v62.2,26.4 | 48.95,26.35 v49.2,26.6 | C3.1 v49.45,33.4 | 97.8,24.48 U4.2 | U4.11 97.8,24.48 | 97.8,24.48 U4.EP | C37.1 v104.2,25.8 | U4.8 96.83,27.2 v95.6,27.2 | U9.2 114,48.95 114,41.2 | 97.8,66.8 R29.1 | 97.8,66.8 X6.C1 97.2,68.8 92.2,68.8 | 92.2,68.8 X6.4 | 91.4,68.8 92.2,68.8 | 91.4,68.8 X6.5 | X6.C4 88.8,68.8 91.4,68.8 | v102.8,53.6 102.8,53.4 C46.1 101.2,53.05 U1.5 | v92.2,46 92.2,46.6 92.6,47 C47.1 93.05,47.05 U1.41 | C61.1 v105.6,48.8 | v99.2,67.4 97.8,67.4 97.8,66.8 | v99.2,72.2 97.2,72.2 X6.C2 | v86.8,72.2 88.8,72.2 X6.C3 | C62.1 93.8,38.58 S2.7 | C66.1 58.8,13.56 S1.25 | U2.4 U2.2 | U7.2 U7.4 | U12.4 U12.2 | 29,35.15 U6.9 | C31.1 v31.2,36 | U6.11 29,36.15 29,35.65 | 29,35.65 U6.10 | U6.8 29,34.65 29,35.15 | 29,35.15 v29,35.4 29,35.65 | R52.1 v32.4,38.8 | C33.1 v32.4,37.4 | R59.2 v21.9,26.5 | U3.9 v47.6,28.2 U3.8 | C9.1 v52.8,18.6
  Top 0.25: C72.1 v21,32.2 | 25.35,35.15 U6.3 | U6.1 24.35,34.15 U6.PADDLE 25.35,35.15 | R13.1 v19.4,28.8 | v17.8,30.2 C23.1 | C73.1 v31.4,32.2 | v14.4,37.2 C69.1 | C70.1 20.2,43 19.6,43 19.6,44 20.9,44 S1.27 | C71.1 v19.2,36 | 25.35,35.15 U6.22 | U6.15 25.85,39.05 v26,39.2 | v14.8,35.4 R55.2
  Top 0.3: R16.1 v22.4,16.4 | v44.95,26.8 45.4,26.35 U3.11 48.95,26.35 | U3.18 48.95,24.35 v49.2,24.6 | U3.21 50.45,24.45 50.6,24.6 50.66,24.6 | U3.27 54.35,24.85 v54.6,24.6 | C2.1 v46,30.6 | C4.1 v58.4,25.4 | U3.31 53.85,26.85 v54.2,27.2 | R5.1 v53.6,35.6 | C13.1 v56,35.6 | U4.2 101,24.48 v101,24.2 101,23.82 U4.1 | U4.11 94.6,24.48 v94.6,24.2 94.6,23.82 U4.12 | C39.1 v93.4,23.6 | C38.1 v101.8,30.6 | C40.1 v93.4,30.6 | R25.1 v89.4,25.15 | C36.1 v99.6,30.6 | U2C.2 73.19,23.45 U2B.7 72.8,23.78 72.8,23.8 72.6,23.8 C44.1 | v76.8,31.4 U7.2 | C43.1 61.39,34.4 v61.6,34.4 | C42.1 61.39,39.8 v61.6,39.8 | C41.1 v60.4,41.2 | U2.2 v56.4,39.6 | U12.2 v105.8,59.8 | C59.1 v111.6,61.2 | C60.1 v111,57.4 | S1.28 15.86,44 | C1.1 v42.2,32.6 | R7.1 v34.2,30.2 | v34.2,22.2 R8.1 | v31.4,27.8 MX1.P v31.4,23.4 | R11.1 v21,29 | R12.1 v31.4,29 | C65.1 7,44.04 S1.32 | U8.4 U8.2 v10.6,40.8 | C6.1 v41,16.8 | S1.13 38.47,13.56 | L2.5 23.86,19.9 v22.4,19.9 | C21.1 v19.1,24.9 | C20.1 v15.1,24.9 | C30.2 v10.6,19.8
  Top 0.4: v12.8,16.4 R14.1
  Top 0.5: R24.1 v92.8,17.8 | C35.2 v98.6,18.4 | v2.6,59 2.6,57.91 VD3.A 8.6,57.91 v8.6,59 | v8.6,60.47 C57.1 12,60.47 v12,62 | U11.3 v18.4,62.4 U11.6 | 25,60.6 C58.1 | 25,60.6 v23,60.6 21.75,60.6 U11.5 | 25,60.6 v27.2,60.6 | R36.1 27.19,44.04 S1.23 | 38.47,13.56 L7.5
  Bottom 0.2: v54.6,24.6 54.8,24.6 | v54.2,27.2 54.4,27.2 | v47.6,28.2 47.4,28.2 | v46.45,19.95 46.45,20.15 | v47.8,20.4 48,20.4 | v47.8,16.2 47.8,16.8 | v49.6,16.4 49.6,16.2 | v52.8,18.6 52.8,18.4 | v54.4,18 54.4,17.8 | v55.8,18 55.8,17.8 | v51.2,16.4 51.2,16.2 | v55.6,22 55.8,22 | v58.4,25.4 58.6,25.4 | v62.2,26.4 62.2,26.8 | v53.6,35.6 53.2,35.6 | v56,35.6 55.4,35.6 | v49.45,33.4 49.45,33.6 | v92.8,17.8 92.4,17.8 | v98.6,18.4 98.6,18.6 | v101,24.2 101.2,24.2 | v94.6,24.2 94.4,24.2 | v93.4,23.6 93.4,23.4 | v104.2,25.8 104.6,25.8 | v101.8,30.6 101.8,30.4 | v95.6,27.2 95.6,28 | v93.4,30.6 93.4,30.4 | v89.4,25.15 89.3,25.15 | v99.6,30.6 99.6,30.8 | v102.8,53.6 103.4,53.6 | v92.2,46 92.4,46 | v105.6,48.8 105.6,48.6 | v31.2,36 31.2,35.4 | v32.4,38.8 32.2,38.8 | v32.4,37.4 32.2,37.4 | v21.9,26.5 21.9,26.3
  Bottom 0.25: v21,32.2 21.2,32.2 | v19.4,28.8 19.4,29.2 | v17.8,30.2 17.8,30.4 | v31.4,32.2 31.2,32.2 | v14.4,37.2 14.4,37.8 | v19.2,36 18.8,36 | v26,39.2 26,39.4 | v14.8,35.4 15.4,35.4
  Bottom 0.3: v22.4,16.4 22.6,16.4 | 12.4,16.4 v12.8,16.4 | v46,30.6 46,30 | v76.8,31.4 76.8,31.6 | v61.6,34.4 62,34.4 | v61.6,39.8 62,39.8 | v60.4,41.2 60.8,41.2 | v56.4,39.6 56.8,39.6 | v105.8,59.8 106.2,59.8 | v111.6,61.2 111.8,61.2 | v111,57.4 C60.1 | v42.2,32.6 42.2,32.4 | v34.2,30.2 34.2,29.6 | v34.2,22.2 34.2,22.8 | v21,29 21.6,29 | v31.4,29 31.2,29 | v10.6,40.8 10.6,40.4 | v41,16.8 41.2,16.8 | v22.4,19.9 22.5,19.9 | v19.1,24.9 19.1,24.7 | v15.1,24.9 15.1,24.8 | v10.6,19.8 10.7,19.8
  Bottom 0.5: v2.6,59 2.6,59.6 | v8.6,59 v8.6,60.47 | 11.6,62 v12,62 12,63.4 | v18.4,62.4 16.8,62.4 | v23,60.6 23,61.6
  other vias: 51.2,26.6 50.2,25.6 97.8,24.8 27.6,52.8 34.7,62 37.8,62 48.3,64.7 53.2,58.4 45.4,53.4 39.8,51.6 87,67.8 72.4,42.7 72.4,39.6 79.3,37.8 80.3,40.3 51.9,71.6 39.1,73.5 65.7,72.2 65.9,61.1 56.3,61.1 112.1,46.1 53.2,7.5 64.9,12.1 58,1.3 1.7,73.3 11.2,73.2 25.4,73.3 22.9,73.3 13.7,73.2 25.6,35.4 37.8,14.6 39.2,14.6 34.7,58.4 37.7,58.4
  pour Bottom (isolate 0.3): 114.4,74.4 0.6,74.4 0.6,0.6 12.2,0.6 12.2,4.6 40,4.6 40,0.6 90.4,0.6 90.4,4.6 103.6,4.6 103.6,0.6 114.4,0.6
  pour Top (isolate 0.3): 0.6,0.6 0.6,74.4 66.4,74.4 66.4,47 114.4,47 114.4,0.6 103.6,0.6 103.6,4.6 90.4,4.6 90.4,0.6 57.1,0.6 57.1,2.8 42.6,2.8 42.6,0.6 40,0.6 40,4.6 12.2,4.6 12.2,0.6
KONTRAST
  Top 0.2: X10.17 60.78,59.9 | 60.78,59.9 R41.1 | 60.78,59.9 R44.2
LO+3,3V  (via drill 0.4 pad 0.8)
  Top 0.2: C73.2 29.5,32.2 29.8,31.9 29.8,31.3 30.1,31 30.1,30.6 R51.1 | 22.8,32.2 22.8,31.5 22.4,31.1 22.4,30.6 R40.1
  Top 0.25: U6.6 26.85,32.55 27.2,32.2 C73.2 29,33.2 v28.4,33.2 | U6.2 24.85,32.45 24.6,32.2 C72.2 22.8,32.2 v22.8,33.2 16.4,33.2 16.4,37 18.34,37 | U6.21 21.6,35.65 C71.2 21.6,36.6 21.2,37 18.34,37 | 18.34,37 L6.2
  Top 0.3: C32.1 21.8,40.6 21.01,39.81 C70.2 L6.2
  Bottom 0.25: v22.8,33.2 23.4,32.6 27.8,32.6 v28.4,33.2
LO_CLK  (via drill 0.4 pad 0.8)
  Top 0.2: v37.4,47.6 38.3,46.7 66.2,46.7 67.5,45.4 68.6,45.4 70.2,47 v70.2,47.5 | v74.6,46.4 74.9,46.1 89.3,46.1 91.05,47.85 U1.37
  Bottom 0.2: v37.4,47.6 36.9,48.1 26.5,48.1 23.8,45.4 23.8,43.1 24.6,42.3 R56.2 | v74.6,46.4 73.5,47.5 v70.2,47.5
LO_DATA  (via drill 0.4 pad 0.8)
  Top 0.2: v38.4,48.6 39.4,48.6 40.8,47.2 66.4,47.2 67.6,46 68.5,46 68.9,46.4 68.9,47.5 69.8,48.4 v71,48.4 | v76.1,47.4 76.4,47.7 85.1,47.7 88.45,51.05 U1.36
  Bottom 0.2: v38.4,48.6 26.3,48.6 23.3,45.6 23.3,42.8 23.2,42.7 R57.2 | v71,48.4 71.4,48 75.5,48 v76.1,47.4
LO_LE  (via drill 0.4 pad 0.8)
  Top 0.2: v80.3,61 84.2,61 85.4,59.8 86.3,59.8 86.7,59.4 91.3,59.4 91.55,59.15 U1.23
  Bottom 0.2: v80.3,61 79.8,60.5 74.1,60.5 73.7,60.1 65.1,60.1 64.4,60.8 62.6,60.8 62,60.2 55.2,60.2 54.8,60.6 54.5,60.6 31.9,60.6 30.5,59.2 30.5,50.9 28.7,49.1 26.1,49.1 22.8,45.8 22.8,43.3 21.7,42.2 R58.2
LO_MUX  (via drill 0.4 pad 0.8)
  Top 0.2: U6.20 22.45,36.15 22.3,36.3 22.3,36.9 21.4,37.8 v19.4,37.8 | v17.4,37.8 16.4,37.8 15,36.4 14.3,36.4 13.2,35.3 13.2,33.8 11.9,32.5 JP3.1
  Bottom 0.2: v17.4,37.8 v19.4,37.8
LOCKDET  (via drill 0.4 pad 0.8)
  Top 0.2: C66.2 R21.1 58.8,18.7 v59,18.7 | v71.3,19.3 70.8,19.8 70.8,42.7 71.8,43.7 74.1,43.7 74.6,43.2 74.6,41.1 75.3,40.4 77.3,40.4 77.8,40.9 79.3,40.9 80.5,42.1 94.3,42.1 97.5,45.3 97.5,48.2 98.5,49.2 v98.5,49.8 | v94.2,56.2 94.55,56.55 U1.17
  Bottom 0.2: v59,18.7 59.6,19.3 v71.3,19.3 | v94.2,56.2 94.2,56.1 95,55.3 96.2,55.3 99.1,52.4 99.1,50.4 v98.5,49.8
N$1
  Top 0.2: R18.2 58.25,32.4 56.6,30.75 54.7,30.75 53.65,29.7 51.5,29.7 50.95,29.15 U3.3
N$2
  Top 0.2: C8.2 55.8,21 55.6,21.2 54.2,21.2 54,21.4 54,22 53.8,22.2 C7.2 52.2,22.2 51.95,22.45 U3.24
N$3
  Top 0.2: C10.2 53,20.4 52.8,20.6 C9.2 52.2,21 51.45,21.75 U3.23
N$4
  Top 0.2: C12.2 49.25,20.25 C11.2 49.45,21.65 U3.19
N$5
  Top 0.2: R1.1 51.2,21.2 50.95,21.45 U3.22
N$6
  Top 0.2: U6.23 22.35,34.65 22,35 18.2,35 17.8,35.4 R55.1
N$7
  Top 0.2: R2.1 52.6,30.45 52.35,30.2 51.3,30.2 50.45,29.35 U3.4
N$8
  Top 0.2: U3.26 53.7,24.35 54.25,23.8 55.2,23.8 55.4,24 R3.1
N$9
  Top 0.2: U3.20 49.95,19.97 49.96,19.96 49.6,19.6 C15.2 49.6,18.2 49.8,18 52,18 53,17 56.6,17 58,18.4 58,18.45 58,18.55 58,22.6 59.4,24 59.4,33.6 59,34 R6.1
N$10
  Top 0.2: R4.1 C14.1 R5.2
N$11
  Top 0.2: R4.2 51,30.6 49.95,29.55 U3.5
N$12
  Top 0.2: U3.7 48.95,29.25 47.9,30.3 47.9,33.5 50,35.6 C14.2 51,35 51.2,34.8 54.8,34.8 55,34.6 C13.2 R6.2
N$13
  Top 0.3: L2.3 29.07,22.47 arc90 29.9,23.3 MX1.6
N$14
  Top 0.2: R19.2 58,31 57.15,30.15 54.9,30.15 53.95,29.2 51.7,29.2 51.45,28.95 U3.2
N$15
  Top 0.2: R20.2 55.15,29.6 54.25,28.7 52,28.7 51.95,28.65 U3.1
N$16  (via drill 0.4 pad 0.8)
  Top 0.2: U6.17 24.85,38.35 24.4,38.8 v24.4,39
  Bottom 0.2: v24.4,39 24.6,39.2 R56.1
N$17  (via drill 0.4 pad 0.8)
  Top 0.2: U6.18 23.75,37.65 23.2,38.2 v23.2,39
  Bottom 0.2: v23.2,39 R57.1
N$18
  Top 0.3: L2.1 29.43,19.93 arc90 32.9,23.4 MX1.1
N$19
  Top 0.25: U6.4 25.85,32.05 25.4,31.6 C22.2
  Top 0.3: R40.2 C22.2
N$20
  Top 0.3: MX1.3 34.2,26.55 | 34.2,26.55 39.65,26.55 40,26.2 C16.1 | 34.2,26.55 R7.2
N$21
  Top 0.3: 34.2,25.6 MX1.2 | 34.2,25.6 39,25.6 40,24.6 C17.1 | R8.2 34.2,25.6
N$22
  Top 0.3: L4.2 C30.1 13.6,19.8 arc-90 15.2,18.3 R14.2
  Top 0.5: R14.2 R15.2
N$23
  Top 0.25: U6.5 26.35,32.05 27,31.4 C19.2
  Top 0.3: C19.2 R51.2
N$24
  Top 0.3: C18.1 C21.2 L3.1
N$25
  Top 0.3: L3.2 C20.2 L4.1
N$26
  Top 0.3: R11.2 C22.1 25.4,28.2 arc90 28.2,25.6 MX1.5
N$27
  Top 0.5: X2.A R15.1 R16.2
N$28
  Top 0.3: R12.2 C19.1 27,28.2 arc90 28.65,26.55 MX1.4
N$29
  Top 0.25: R13.2 C29.1
N$30  (via drill 0.4 pad 0.8)
  Top 0.25: R39.2 33,34.4 v30,34.4 | U6.24 21.55,34.15 v21.4,34 C29.2 C23.2
  Bottom 0.25: v30,34.4 30,33.6 28.4,32 22.6,32 21.4,33.2 v21.4,34
N$31
  Top 0.2: U6.7 28.85,34.15 29.4,33.6 C31.2 R39.1
N$32
  Top 0.25: U6.14 26.35,38.35 26.9,38.9 26.9,40.6 C32.2
N$33
  Top 0.2: U6.13 28.25,37.65 29.4,38.8 R52.2
N$34
  Top 0.2: U6.12 28.65,36.65 29.4,37.4 C33.2
N$35
  Top 0.25: U6.16 25.35,38.65 25.2,38.8 25.2,41.4 25.8,42 34.6,42 35.4,41.2 C34.1
N$36
  Top 0.3: U8.1 14.4,39.63 C69.2 14.4,39.8 L6.1
N$37
  Top 0.3: L7.1 38.47,21.6
  Top 0.4: 38.47,21.6 C75.2
N$38
  Top 0.3: 35.93,16.4 L7.4
  Top 0.5: X1.A 33.6,14.8 arc-90 35.2,16.4 35.93,16.4
N$39
  Top 0.4: L7.3 35.93,22.93 arc-90 36.4,23.4 C74.2
N$40
  Top 0.2: C25.1 58.2,26.8 57.8,27.2 56.15,27.2 54.8,25.85 U3.29
N$41  (via drill 0.4 pad 0.8)
  Top 0.2: U6.19 23.35,37.15 21.7,38.8 v21.7,39.1
  Bottom 0.2: R58.1 v21.7,39.1
N$42
  Top 0.2: U3.25 53.5,23.85 54.05,23.3 55.1,23.3 55.5,22.9 56.5,22.9 57.2,22.2 R21.2
N$43
  Top 0.2: R22.2 58.2,28.2 57.8,27.8 56,27.8 54.55,26.35 U3.30
N$44  (via drill 0.4 pad 0.8)
  Top 0.3: R23.1 v60.25,17.8 | U2B.8 80.81,23.45 U2C.3
  Bottom 0.3: U2B.8 U2A.8 80.81,19.81 78.8,17.8 71,17.8 70.1,18.7 61.15,18.7 v60.25,17.8
N$45
  Top 0.5: X3.A C27.2
N$46
  Top 0.5: R24.2 C27.1 C28.2
N$47
  Top 0.3: U4.14 97.47,21.88 97,21.4 C28.1
N$48
  Top 0.3: U4.15 98.12,21.88 98.6,21.4 C35.1
N$49
  Top 0.2: U4.5 98.78,27.98 99,28.2 C36.2
N$50
  Top 0.2: U4.10 91.8,25.12 R25.2
N$51
  Top 0.2: U4.7 97.47,28.2 R26.2 98.12,28.2 U4.6
N$52
  Top 0.3: C42.2 57.6,38.4 L1.1 54.43,38.14 U2.1
N$53
  Top 0.2: X6.3 93,64.8 92.6,64.4 92.6,64.2 | 92.6,64.2 R27.2 | R31.2 92.6,64.2
N$54
  Top 0.2: X6.2 93.8,64.8 94.2,64.4 R28.2
N$55
  Top 0.2: X6.1 94.6,65.6 96,64.2 R30.1
N$56
  Top 0.2: U1.19 93.55,60.35 94.2,61 R28.1
N$57
  Top 0.2: U1.20 93.05,60.35 92.6,60.8 R27.1
N$58
  Top 0.2: T1.3 87,64.2 R31.1
N$59
  Top 0.2: 86.06,61.2 T1.1 | 86.06,61.2 R33.2 | 86.06,61.2 86.06,60.54 86.3,60.3 88.5,60.3 90,61.8 R32.1
N$60
  Top 0.2: U1.6 99.55,53.55 100.2,54.2 102,54.2 103.2,55.4 C48.1
N$61
  Top 0.2: R34.2 C48.2
N$62
  Top 0.2: R34.1 107.6,48.95 U9.3
N$63
  Top 0.3: U10.1 31.41,58.01 31.2,57.8 C50.1
N$64
  Top 0.3: U10.3 31.53,55.47 31.19,55.81 C50.2
N$65
  Top 0.3: U10.4 C51.2
N$66
  Top 0.3: U10.5 31.93,52.93 31.2,52.2 C51.1
N$67
  Top 0.3: U10.6 32.06,51.66 30.99,50.59 C52.2
N$68
  Top 0.3: U10.2 32.91,56.8 28.8,56.8 28.19,56.19 C53.2
N$69
  Top 0.2: C18.2 R59.1
  Top 0.3: L2.4 23.86,22.5 C18.2
N$70  (via drill 0.4 pad 0.8)
  Top 0.2: v61,16 61.4,16.4 61.4,24 61,24.4 61,26.3 62,27.3 62,28.1 61.6,28.5 60.8,28.5 60.5,28.2 R22.1
  Bottom 0.2: v61,16 60.2,16 59.2,15 JP1.1
N$71
  Top 0.3: U3.15 45.95,24.35 45.2,23.6 | R54.2 42.4,21.6
  Top 0.4: C75.1 42.4,21.6 43.2,21.6 45.2,23.6
N$72
  Top 0.3: U3.14 45.05,24.85 44.4,24.2 | R53.2 40.6,23.4
  Top 0.4: C74.1 40.6,23.4 43.6,23.4 44.4,24.2
N$73
  Top 0.5: VD3.K 5.8,52 L5.1 14.2,52 16.72,54.52 U11.2
N$74
  Top 0.3: U11.4 20.08,56.88 18.8,55.6 18.8,48.4 19.6,47.6 R36.2 25.21,49.41 C56.1 R35.1
N$75  (via drill 0.4 pad 0.8)
  Top 0.2: U1.15 95.55,57.35 96,56.9 v96.5,56.9 | R43.1 103.5,47.57 JP2.2
  Bottom 0.2: v96.5,56.9 96.5,56.4 100.1,52.8 100.1,47.8 100.33,47.57 JP2.2
N$76  (via drill 0.4 pad 0.8)
  Top 0.2: U1.16 95.05,56.55 v95.4,56.2 | R42.1 103.5,45.03 JP2.3
  Bottom 0.2: JP2.3 100.17,45.03 99.6,45.6 99.6,52.6 96.3,55.9 95.7,55.9 v95.4,56.2
N$77  (via drill 0.4 pad 0.8)
  Top 0.2: U1.9 97.25,55.05 96.6,54.4 95.2,54.4 94.4,53.6 91.8,53.6 91.3,54.1 v91.3,54.7
  Bottom 0.2: X10.13 65.86,57.86 66.3,58.3 75.4,58.3 75.8,58.7 81.2,58.7 85.2,54.7 v91.3,54.7
N$78
  Top 0.2: X4.4 83.2,9 83.9,9.7 83.9,9.85 83.9,10 83.9,13.95 82.25,15.6 R48.1
N$79
  Top 0.2: X4.3 79,9 76,12 R47.1
N$80
  Top 0.2: X5.4 71.4,9 74.4,12 R45.1
N$81
  Top 0.2: X5.3 66.6,10.3 66.6,14.2 66.8,14.4 R49.1
N$82
  Top 0.2: X5.6 70.9,4.7 72.2,3.4 77.8,3.4 79,4.6 80.6,4.6 80.9,4.3 | 80.9,4.3 81.8,3.4 85.8,3.4 86.8,4.4 86.8,8.2 86.8,8.45 86.8,8.8 84.4,11.2 84.4,14.2 81.8,16.8 R46.1 | X4.6 82.5,5.9 80.9,4.3
N$83  (via drill 0.4 pad 0.8)
  Top 0.2: R50.1 87.8,4.6 86,2.8 80.4,2.8 80.2,3 v79.8,3.4 79.2,2.8 71.2,2.8 67.9,6.1 X5.5
  Bottom 0.2: X4.5 79.5,3.7 v79.8,3.4
RD  (via drill 0.4 pad 0.8)
  Top 0.2: U1.12 97.8,56.55 v97.8,58.5 | X10.9 70.94,59.34 71.4,59.8 71.7,59.8 71.9,59.8 82.8,59.8 83.7,58.9 v86,58.9
  Bottom 0.2: v97.8,58.5 97.8,59.9 97.2,60.5 96.1,60.5 95.8,60.2 89.6,60.2 89.4,60.2 88.1,58.9 v86,58.9
REFCLK  (via drill 0.4 pad 0.8)
  Top 0.2: 60.25,26.8 C25.2 | 60.25,26.8 R17.2 C26.1 | C34.2 44.4,41.2 49,36.6 55.4,36.6 56,37.2 60,37.2 60.4,36.8 v60.4,34.1 | 60.25,26.8 60.6,26.8 61.2,27.4 v61.2,27.7
  Bottom 0.2: v61.2,27.7 60.1,27.7 59.5,28.3 59.5,33.6 60,34.1 v60.4,34.1
RF+
  Top 0.2: C17.2 R9.2
  Top 0.3: U3.13 44.25,25.35 43.5,24.6 C17.2
RF+3,3V  (via drill 0.4 pad 0.8)
  Top 0.2: R10.1 R9.1 | C4.2 55.95,25.35 | C3.2 U3.6 | 49.4,31.8 49.45,31.75
  Top 0.3: U3.10 46.65,26.85 v46.2,27.3 46,27.5 C2.2 | C5.2 v46.45,23.2 46.45,23.6 46.7,23.85 U3.16 | C5.2 47.15,22.35 47.8,23 U3.17 | R3.2 57,24 56.8,24.2 56.8,25.4 | 56.8,25.4 C4.2 | v56.8,26.4 56.8,25.4 | 55.95,25.35 U3.28 | U3.32 52.8,27.6 53.4,28.2 v55.2,28.2 | 52.6,31.8 v55.2,31.8 56.2,31.8 57.2,32.8 57.2,35 57.6,35.4 L1.2 59.41,36.26 C43.2 | 52.6,31.8 R2.2 | v48.6,31.8 49.4,31.8 52.6,31.8 | v47.2,31.8 47.2,29.4 46.8,29 46.2,29 46,28.8 C2.2 | 49.45,31.75 C3.2 | R10.1 45,29.2 45,28.2 C2.2 | R9.1 C1.2 | R53.1 R54.1 43.6,18.4 C6.2 44.8,16.8 45.2,17.2 45.2,22 45.55,22.35 C5.2
  Bottom 0.2: v46.45,23.2 46.45,27.05 v46.2,27.3
  Bottom 0.3: v56.8,26.4 56.8,27 55.6,28.2 v55.2,28.2 v55.2,31.8 | v47.2,31.8 v48.6,31.8
RF-
  Top 0.2: 43.8,26.2 R10.2
  Top 0.3: U3.12 44.35,25.85 44,26.2 43.8,26.2 C16.2
RXD1  (via drill 0.4 pad 0.8)
  Top 0.2: v78.7,43.2 79.1,43.6 93.7,43.6 96,45.9 96,47.8 95.55,48.25 U1.46 | U10.12 43.47,52.93 45,51.4 45,48.8 45.6,48.2 67.4,48.2 v67.6,48
  Bottom 0.2: v67.6,48 68.3,48 68.9,47.4 68.9,46.7 71.4,44.2 76.2,44.2 77.2,43.2 v78.7,43.2
SWCLK
  Top 0.2: X9.6 52.07,52.33 52.6,51.8 52.6,51.1 53.6,50.1 60.6,50.1 63.1,52.6 73.6,52.6 74.8,51.4 83.6,51.4 86.75,54.55 U1.29
SWDIO  (via drill 0.4 pad 0.8)
  Top 0.2: U1.39 92.05,48.15 89.5,45.6 73.6,45.6 v73,45 | v68.4,48.9 67.2,48.9 67,48.7 53.2,48.7 52.11,49.79 X9.8
  Bottom 0.2: v73,45 72.7,44.7 71.6,44.7 69.4,46.9 69.4,47.9 v68.4,48.9
SWO
  Top 0.2: U1.28 86.45,55.05 83.3,51.9 75.1,51.9 73.9,53.1 62.8,53.1 60.4,50.7 53.8,50.7 53.1,51.4 53.1,54.1 52.33,54.87 X9.4
TXD1  (via drill 0.4 pad 0.8)
  Top 0.2: U10.11 43.94,51.66 44.5,51.1 44.5,48.5 45.3,47.7 66.6,47.7 67.4,46.9 v68,46.9 | v77.8,42.3 79.2,42.3 80,43.1 93.9,43.1 96.5,45.7 96.5,48 96.05,48.45 U1.47
  Bottom 0.2: v68,46.9 71.2,43.7 76,43.7 77.4,42.3 v77.8,42.3
USB_CONN
  Top 0.2: U1.22 92.05,59.95 91.8,60.2 R32.2
USB_VBUS
  Top 0.2: U1.14 96.05,61.75 R30.2 R29.2
V24_RXD
  Top 0.3: U10.13 43.8,54.2 46.6,57 46.6,65.4 49.4,68.2 49.4,71 48.73,71.67 X8.1
  Bottom 0.3: CON1.2 69.99,68.41 68.6,69.8 50.8,69.8 48.93,71.67 X8.1
V24_TXD
  Top 0.3: U10.14 44.07,55.47 45.94,57.34 45.94,65.74 47.54,67.34 X8.2
  Bottom 0.3: X8.2 66.07,69.13 67.2,68 CON1.3
WR
  Top 0.2: X10.10 70.94,55.7 75.6,55.7 76,55.3 76,53.6 76.7,52.9 79.8,52.9 81.9,52.9 82.8,52.9 86.45,56.55 U1.25

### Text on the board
Top: GF-4360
